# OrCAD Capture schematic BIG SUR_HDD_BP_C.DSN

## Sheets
1 P01 Cover Page: title: Big Sur; rev: C; company: Quanta
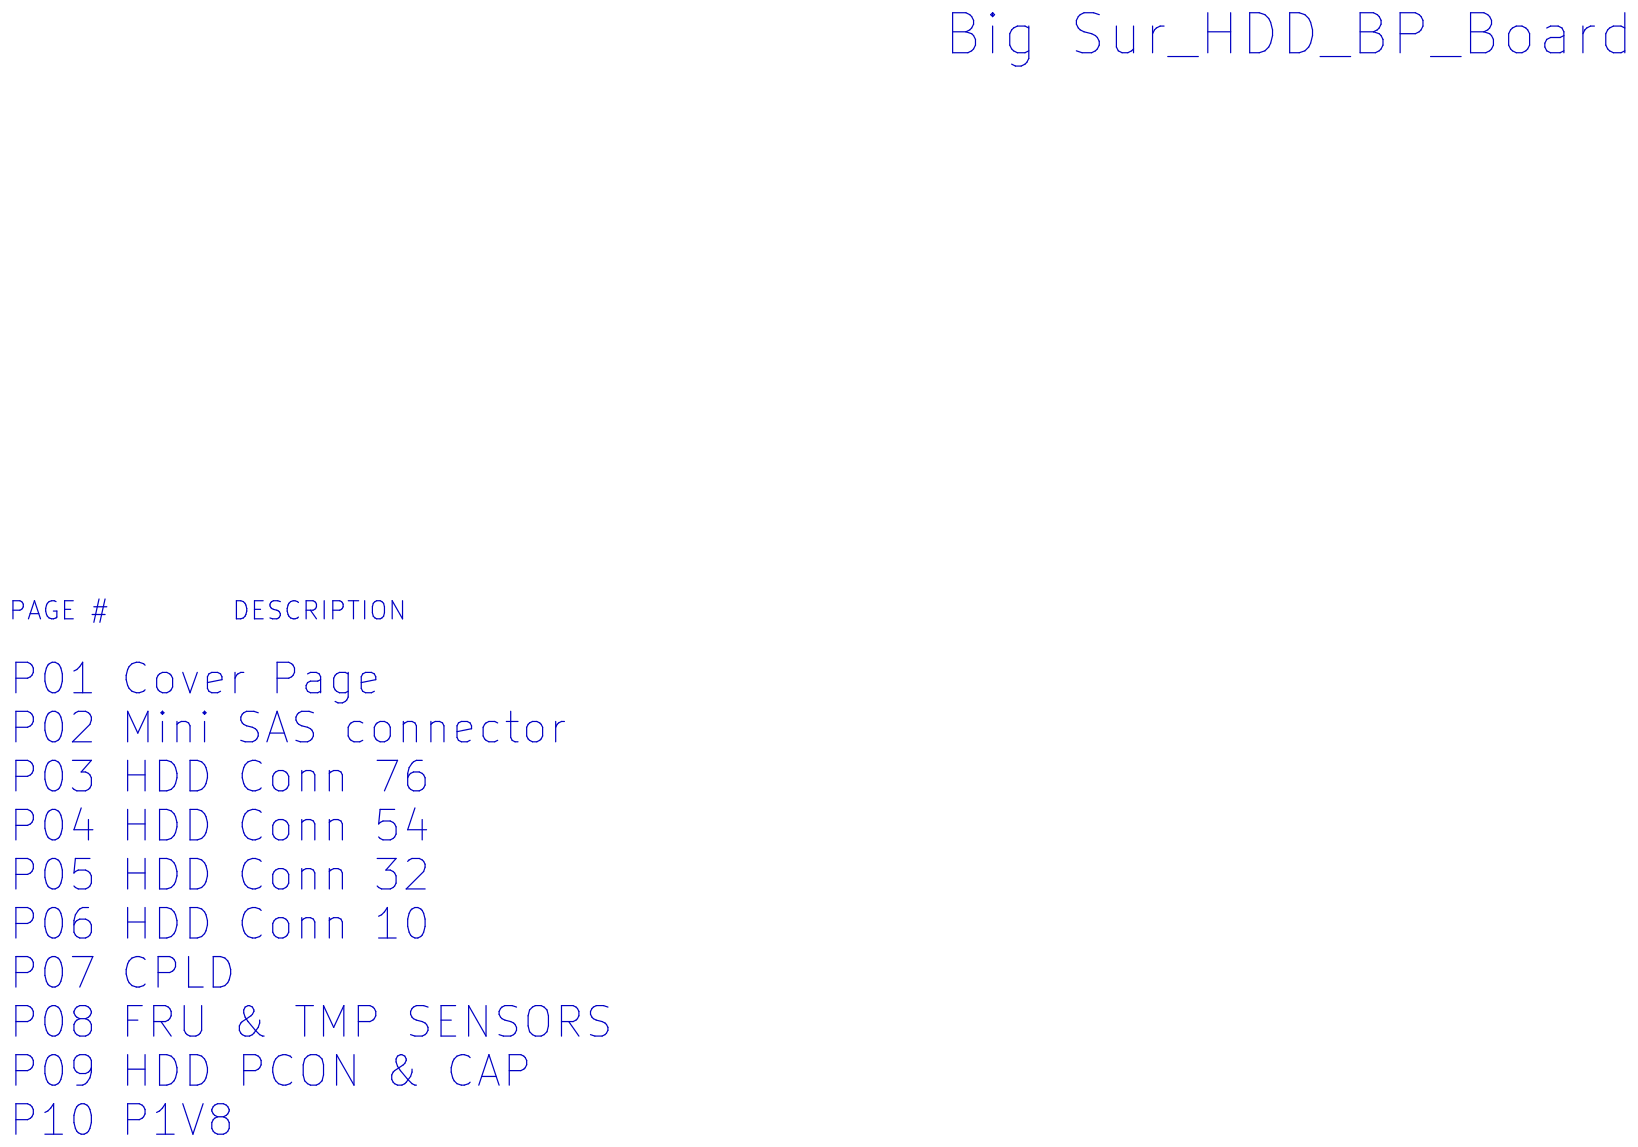
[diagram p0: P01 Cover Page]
2 P10 P1V8: size A
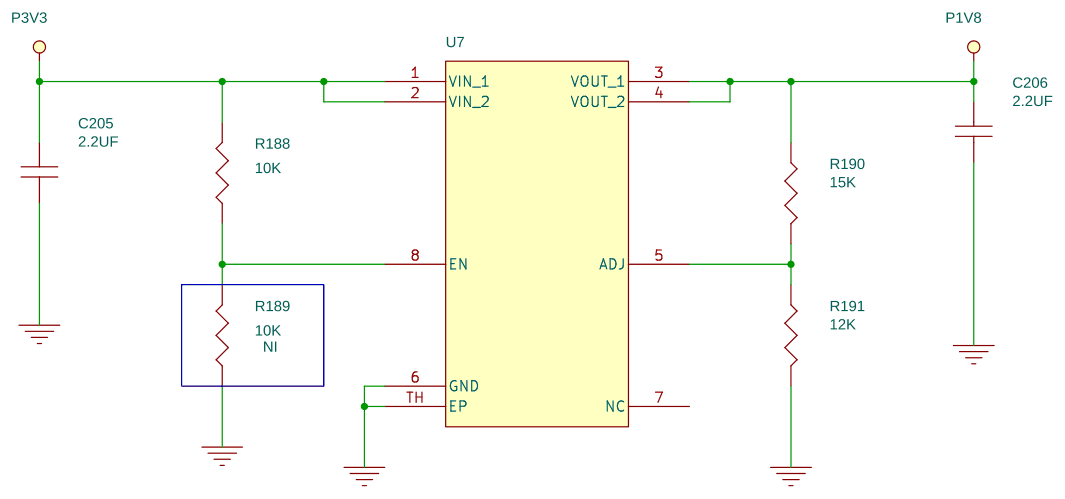
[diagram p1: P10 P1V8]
3 P02 Mini SAS connector: size B
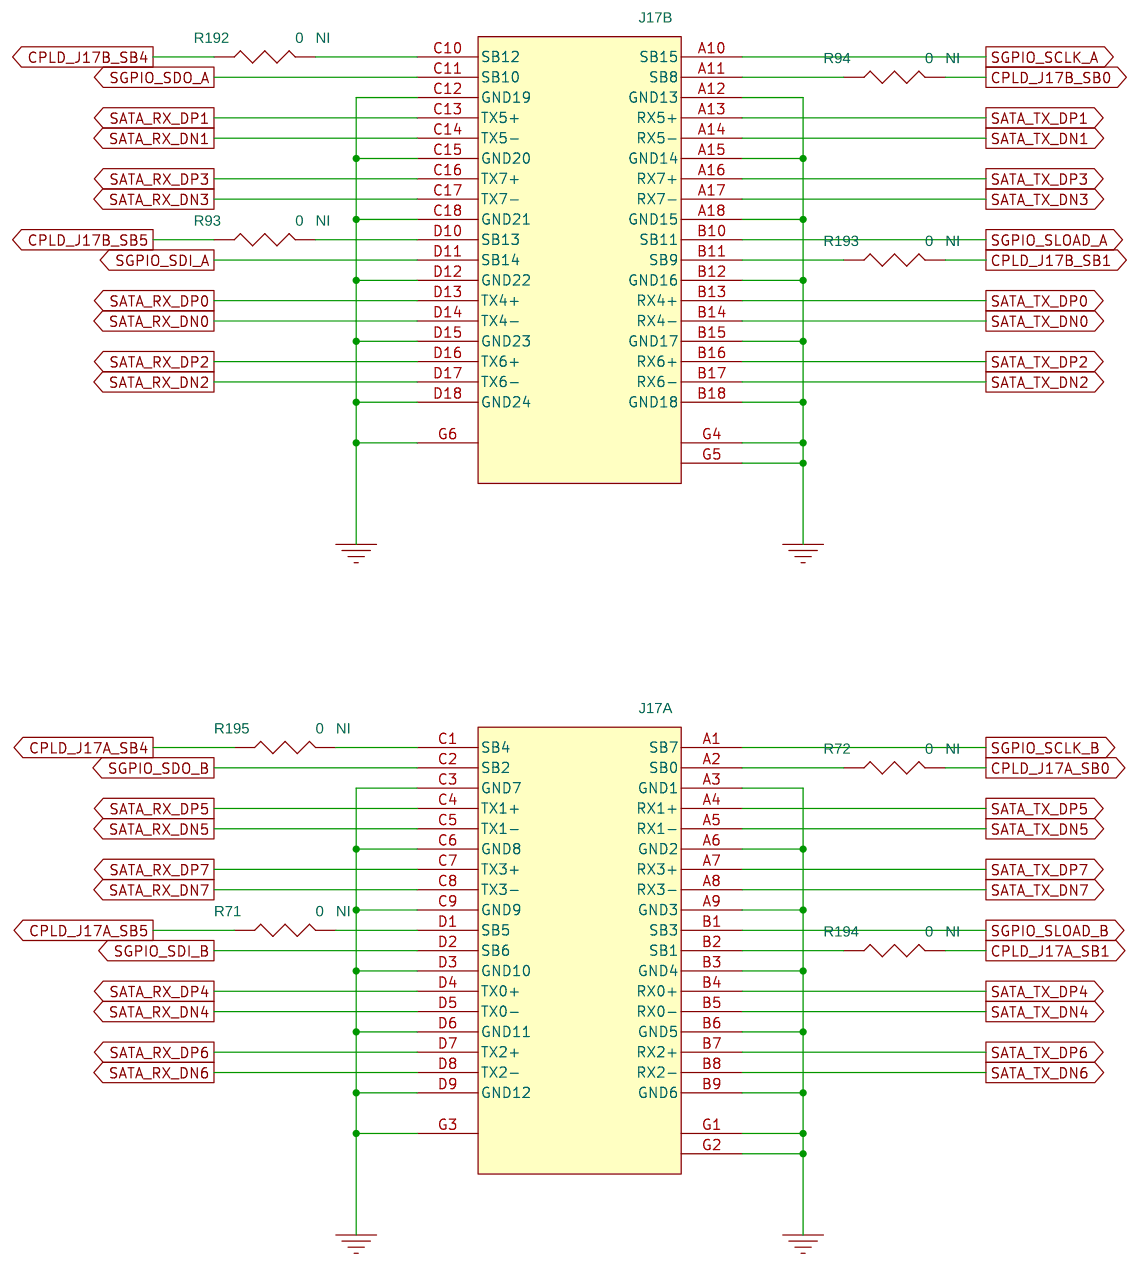
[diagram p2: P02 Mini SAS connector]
4 P03 HDD Conn 76: size C
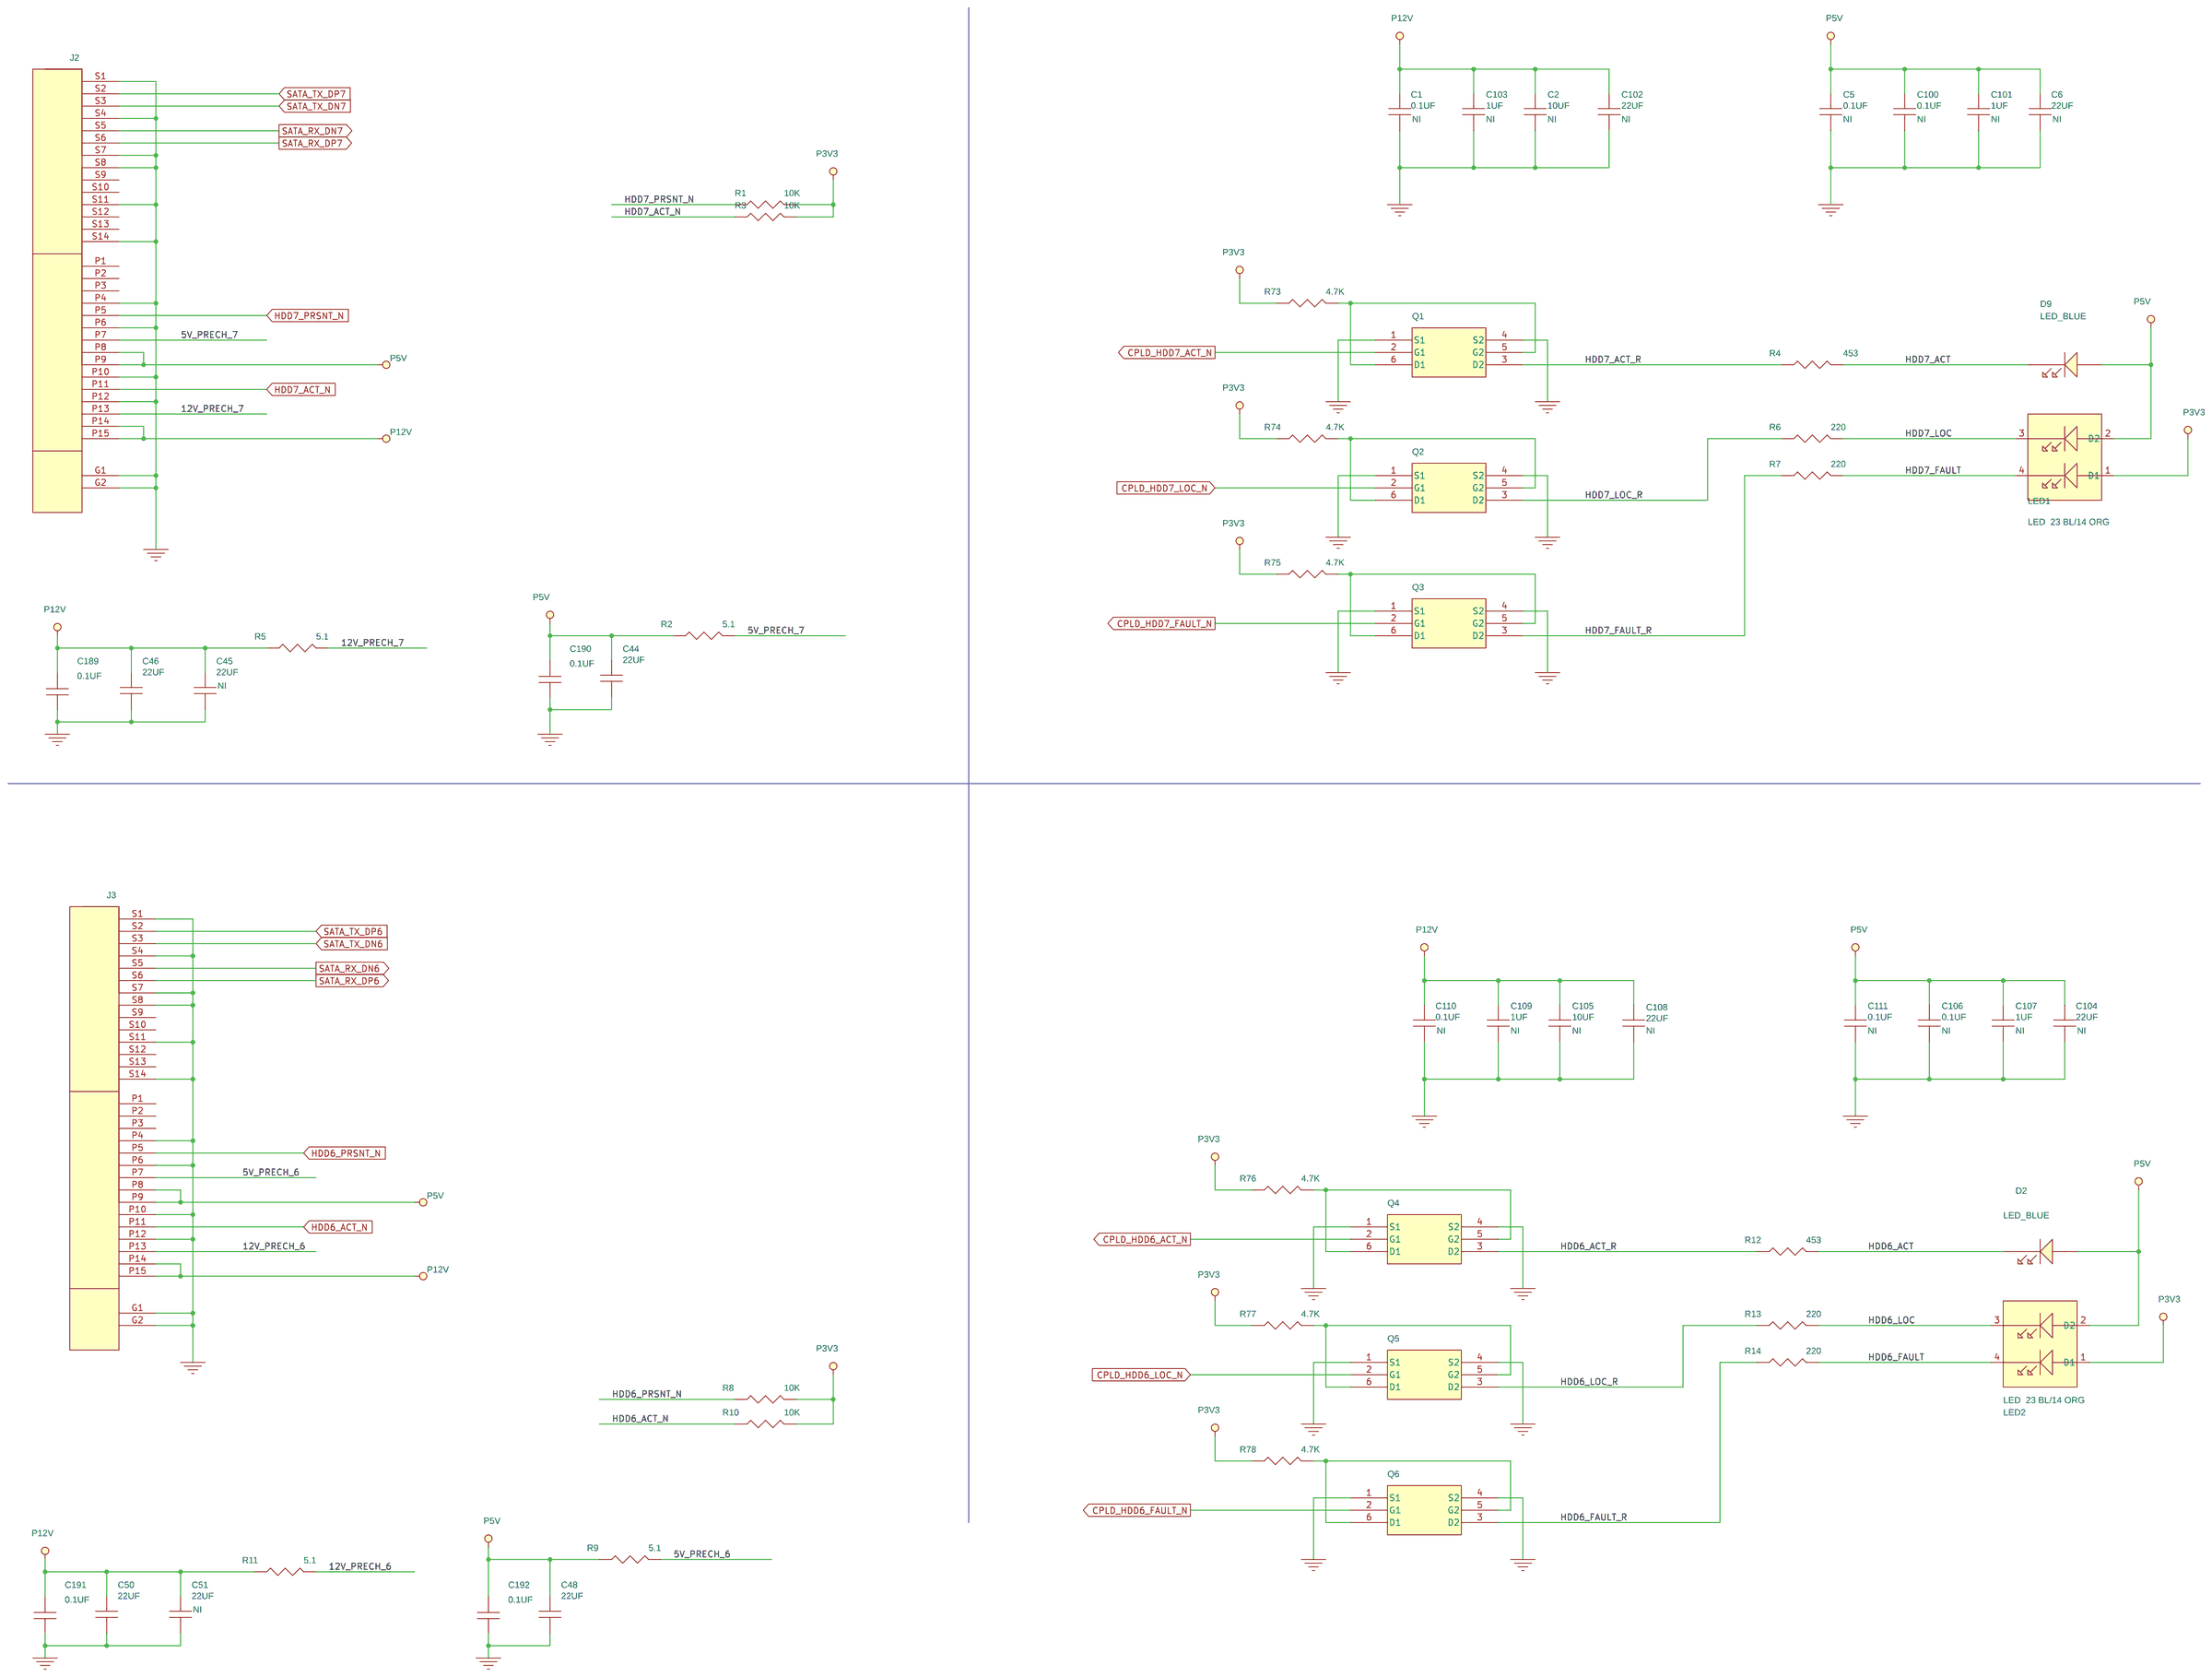
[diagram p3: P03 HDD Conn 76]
5 P04 HDD Conn 54: size C
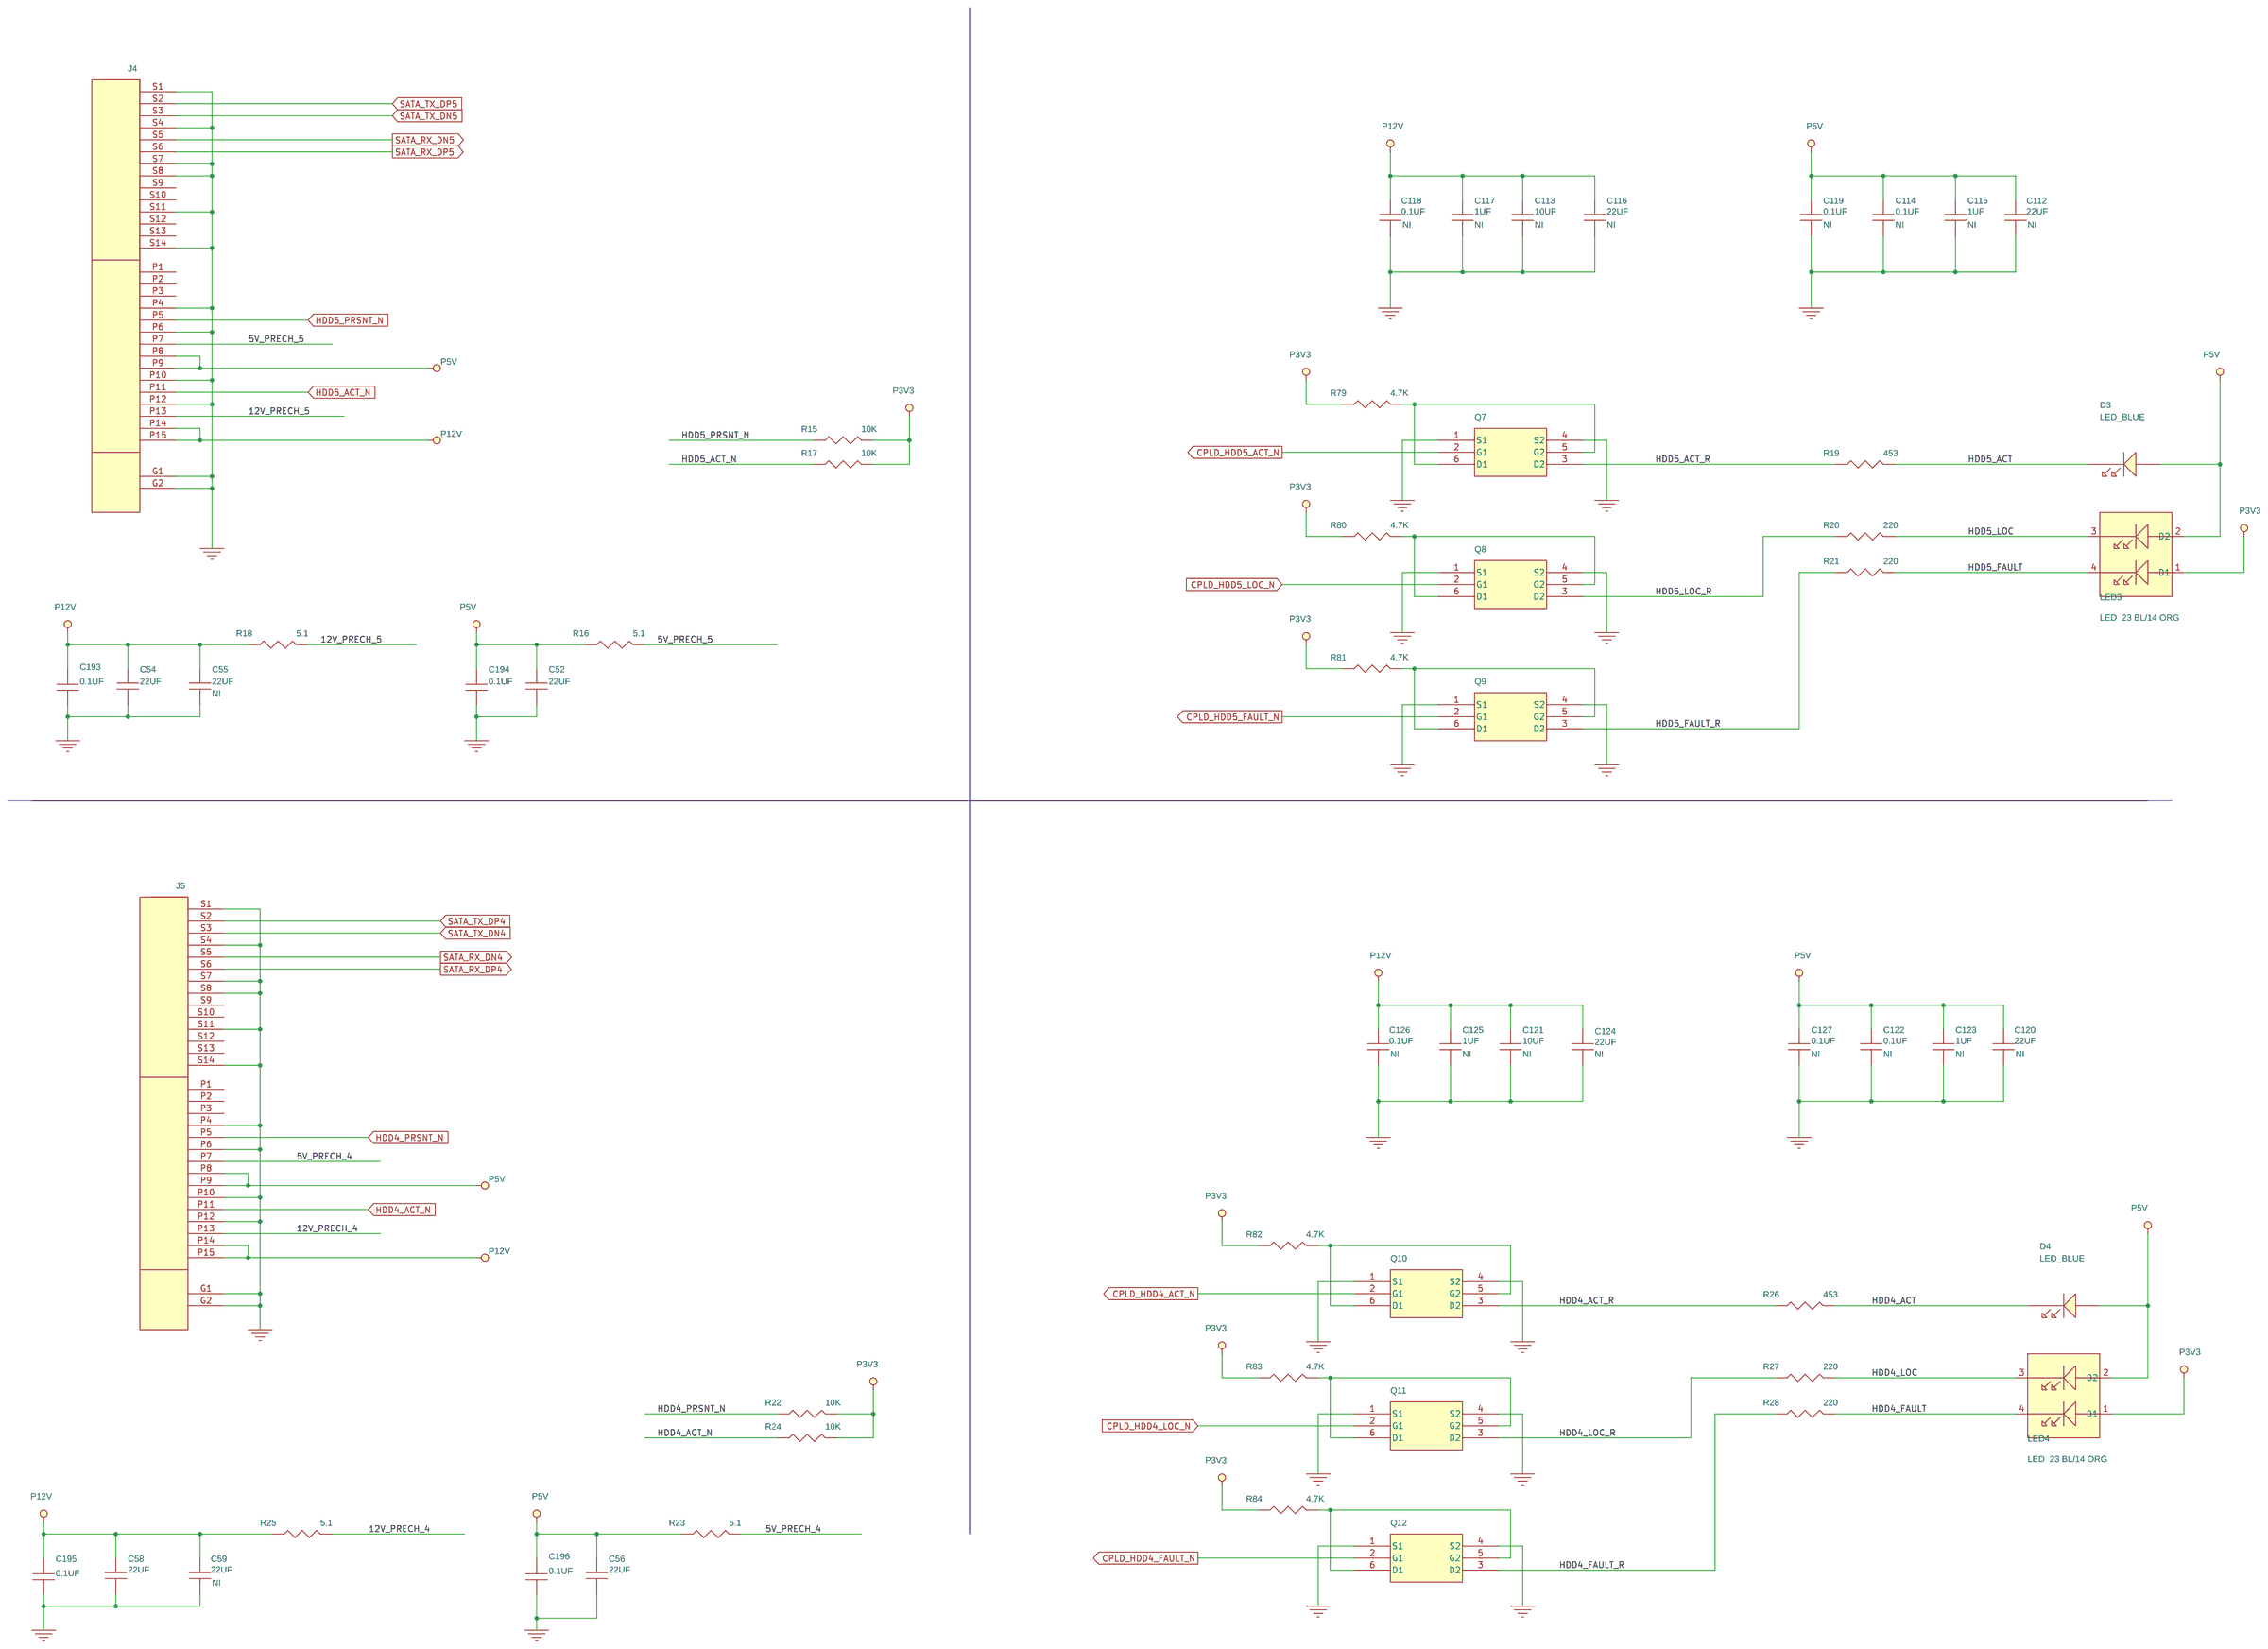
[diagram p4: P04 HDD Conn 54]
6 P05 HDD Conn 32: size C
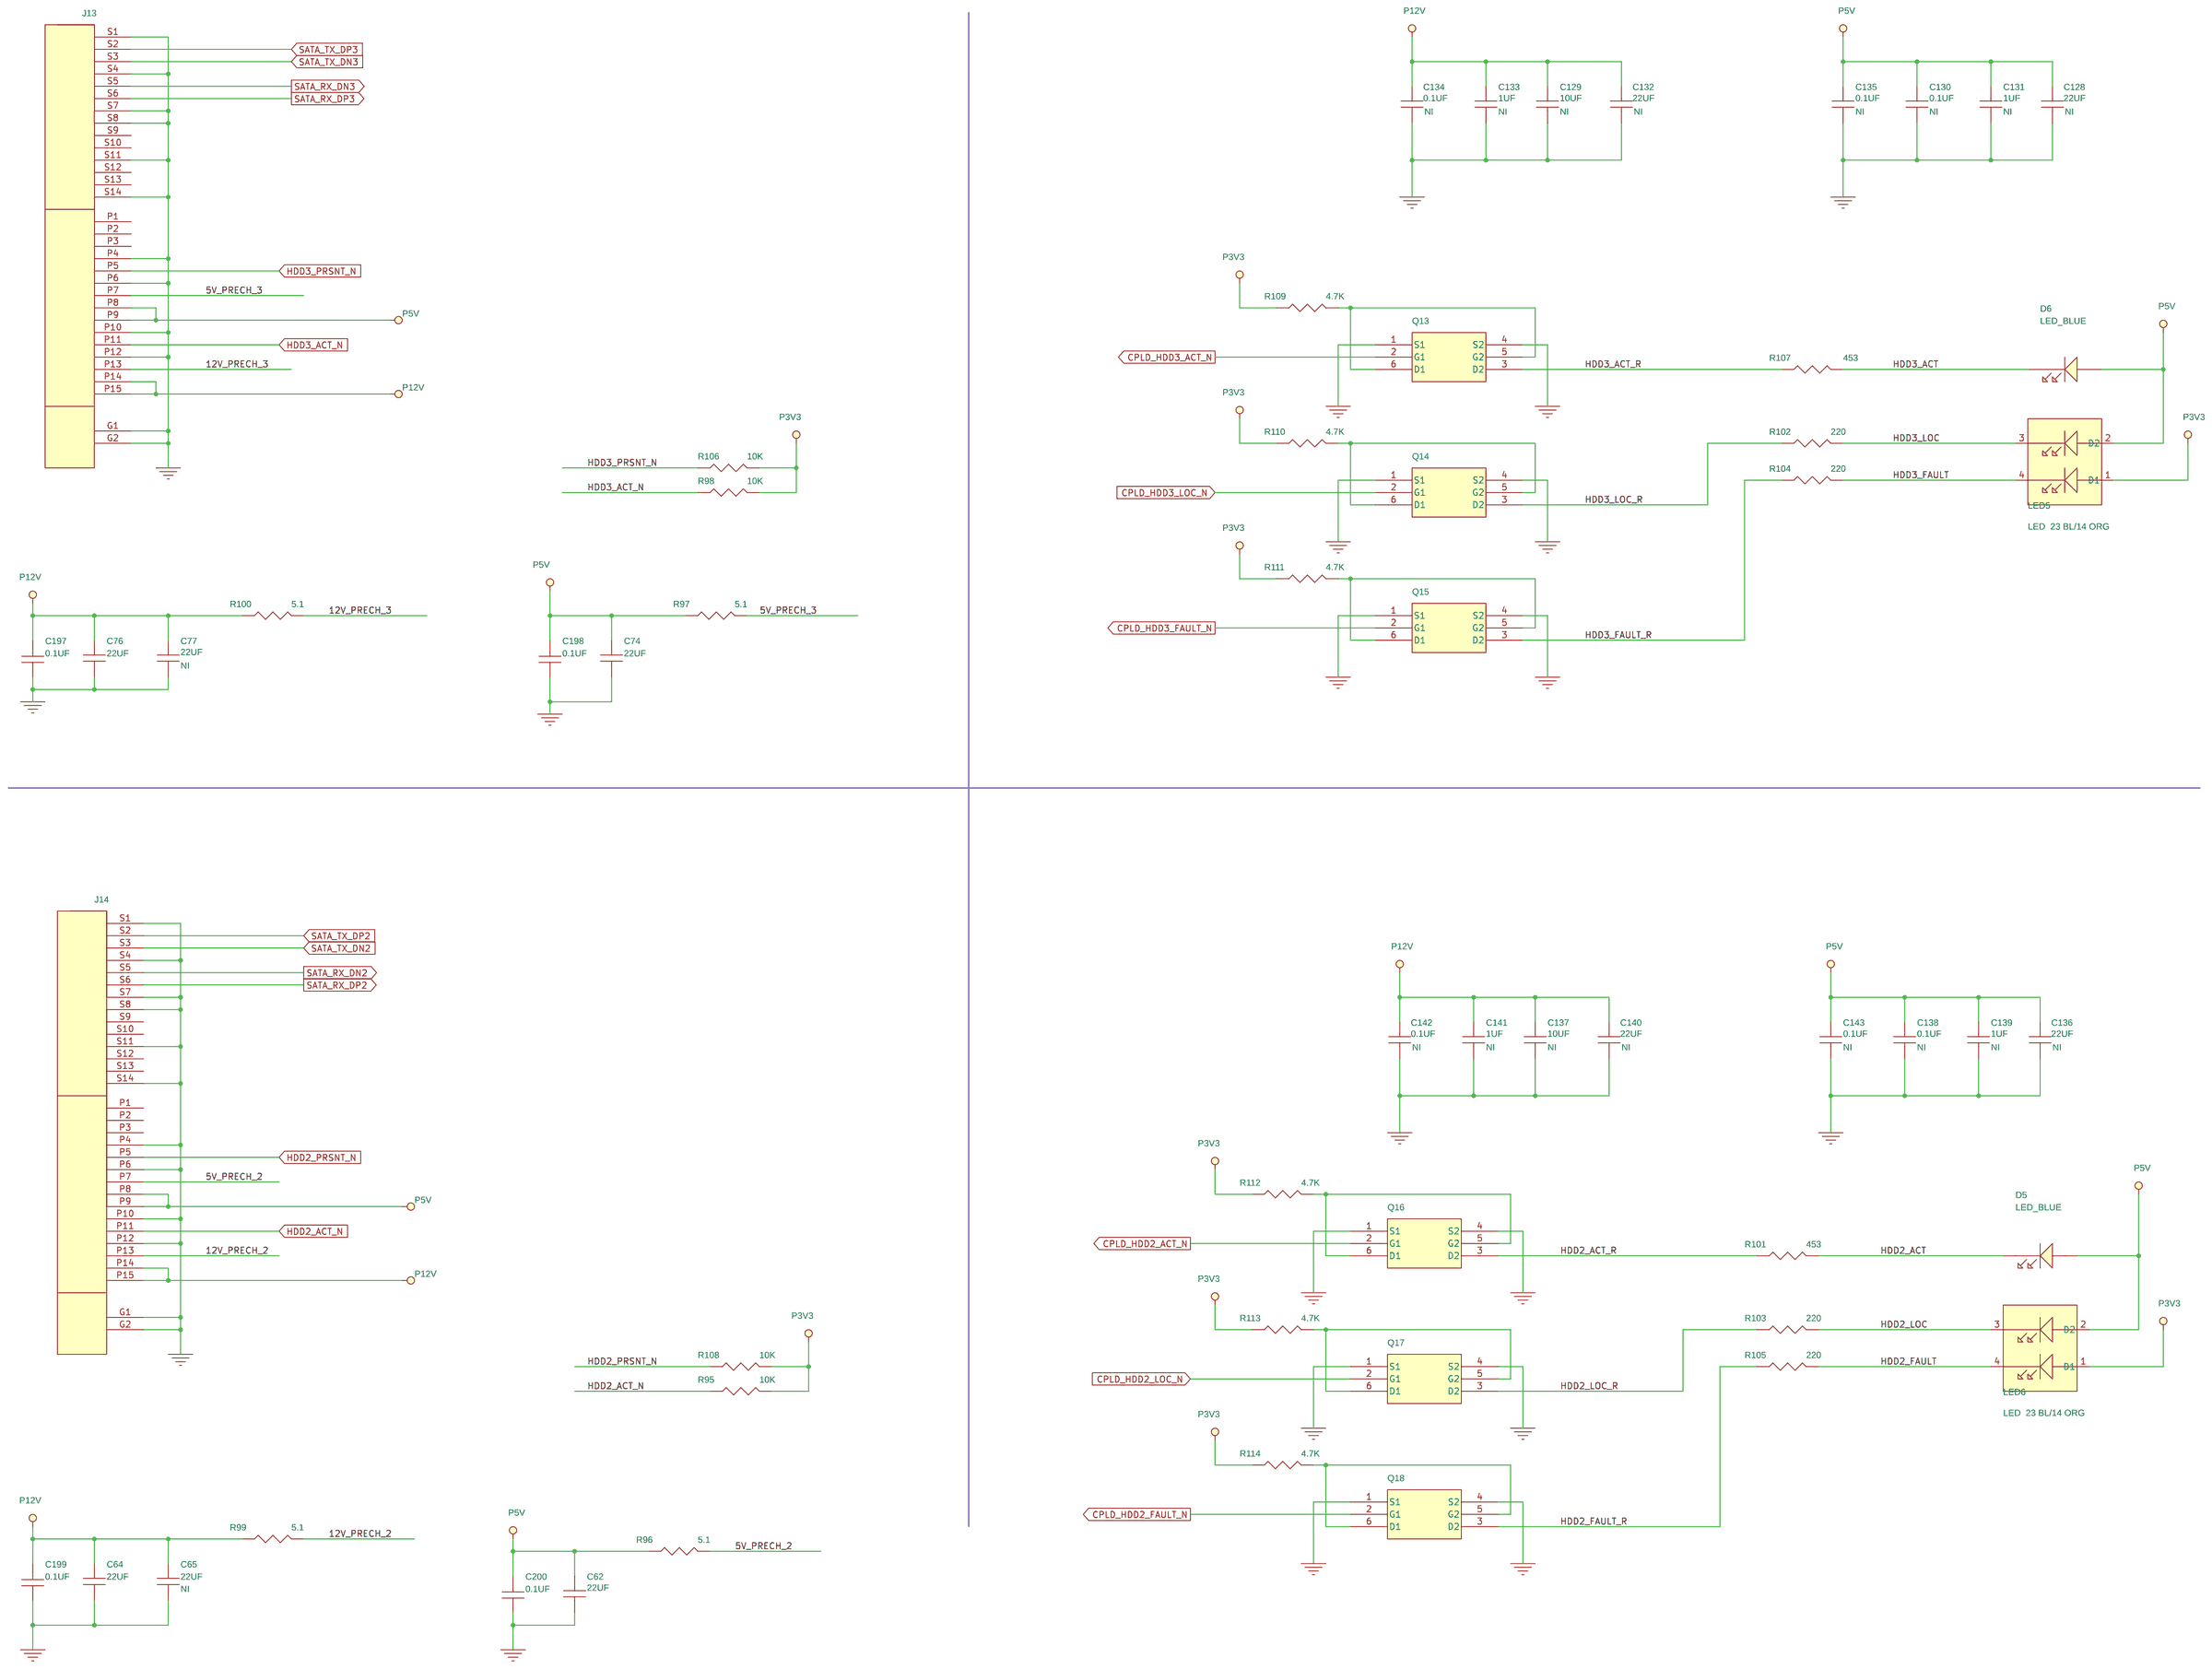
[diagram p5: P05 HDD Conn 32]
7 P06 HDD Conn 10: size C
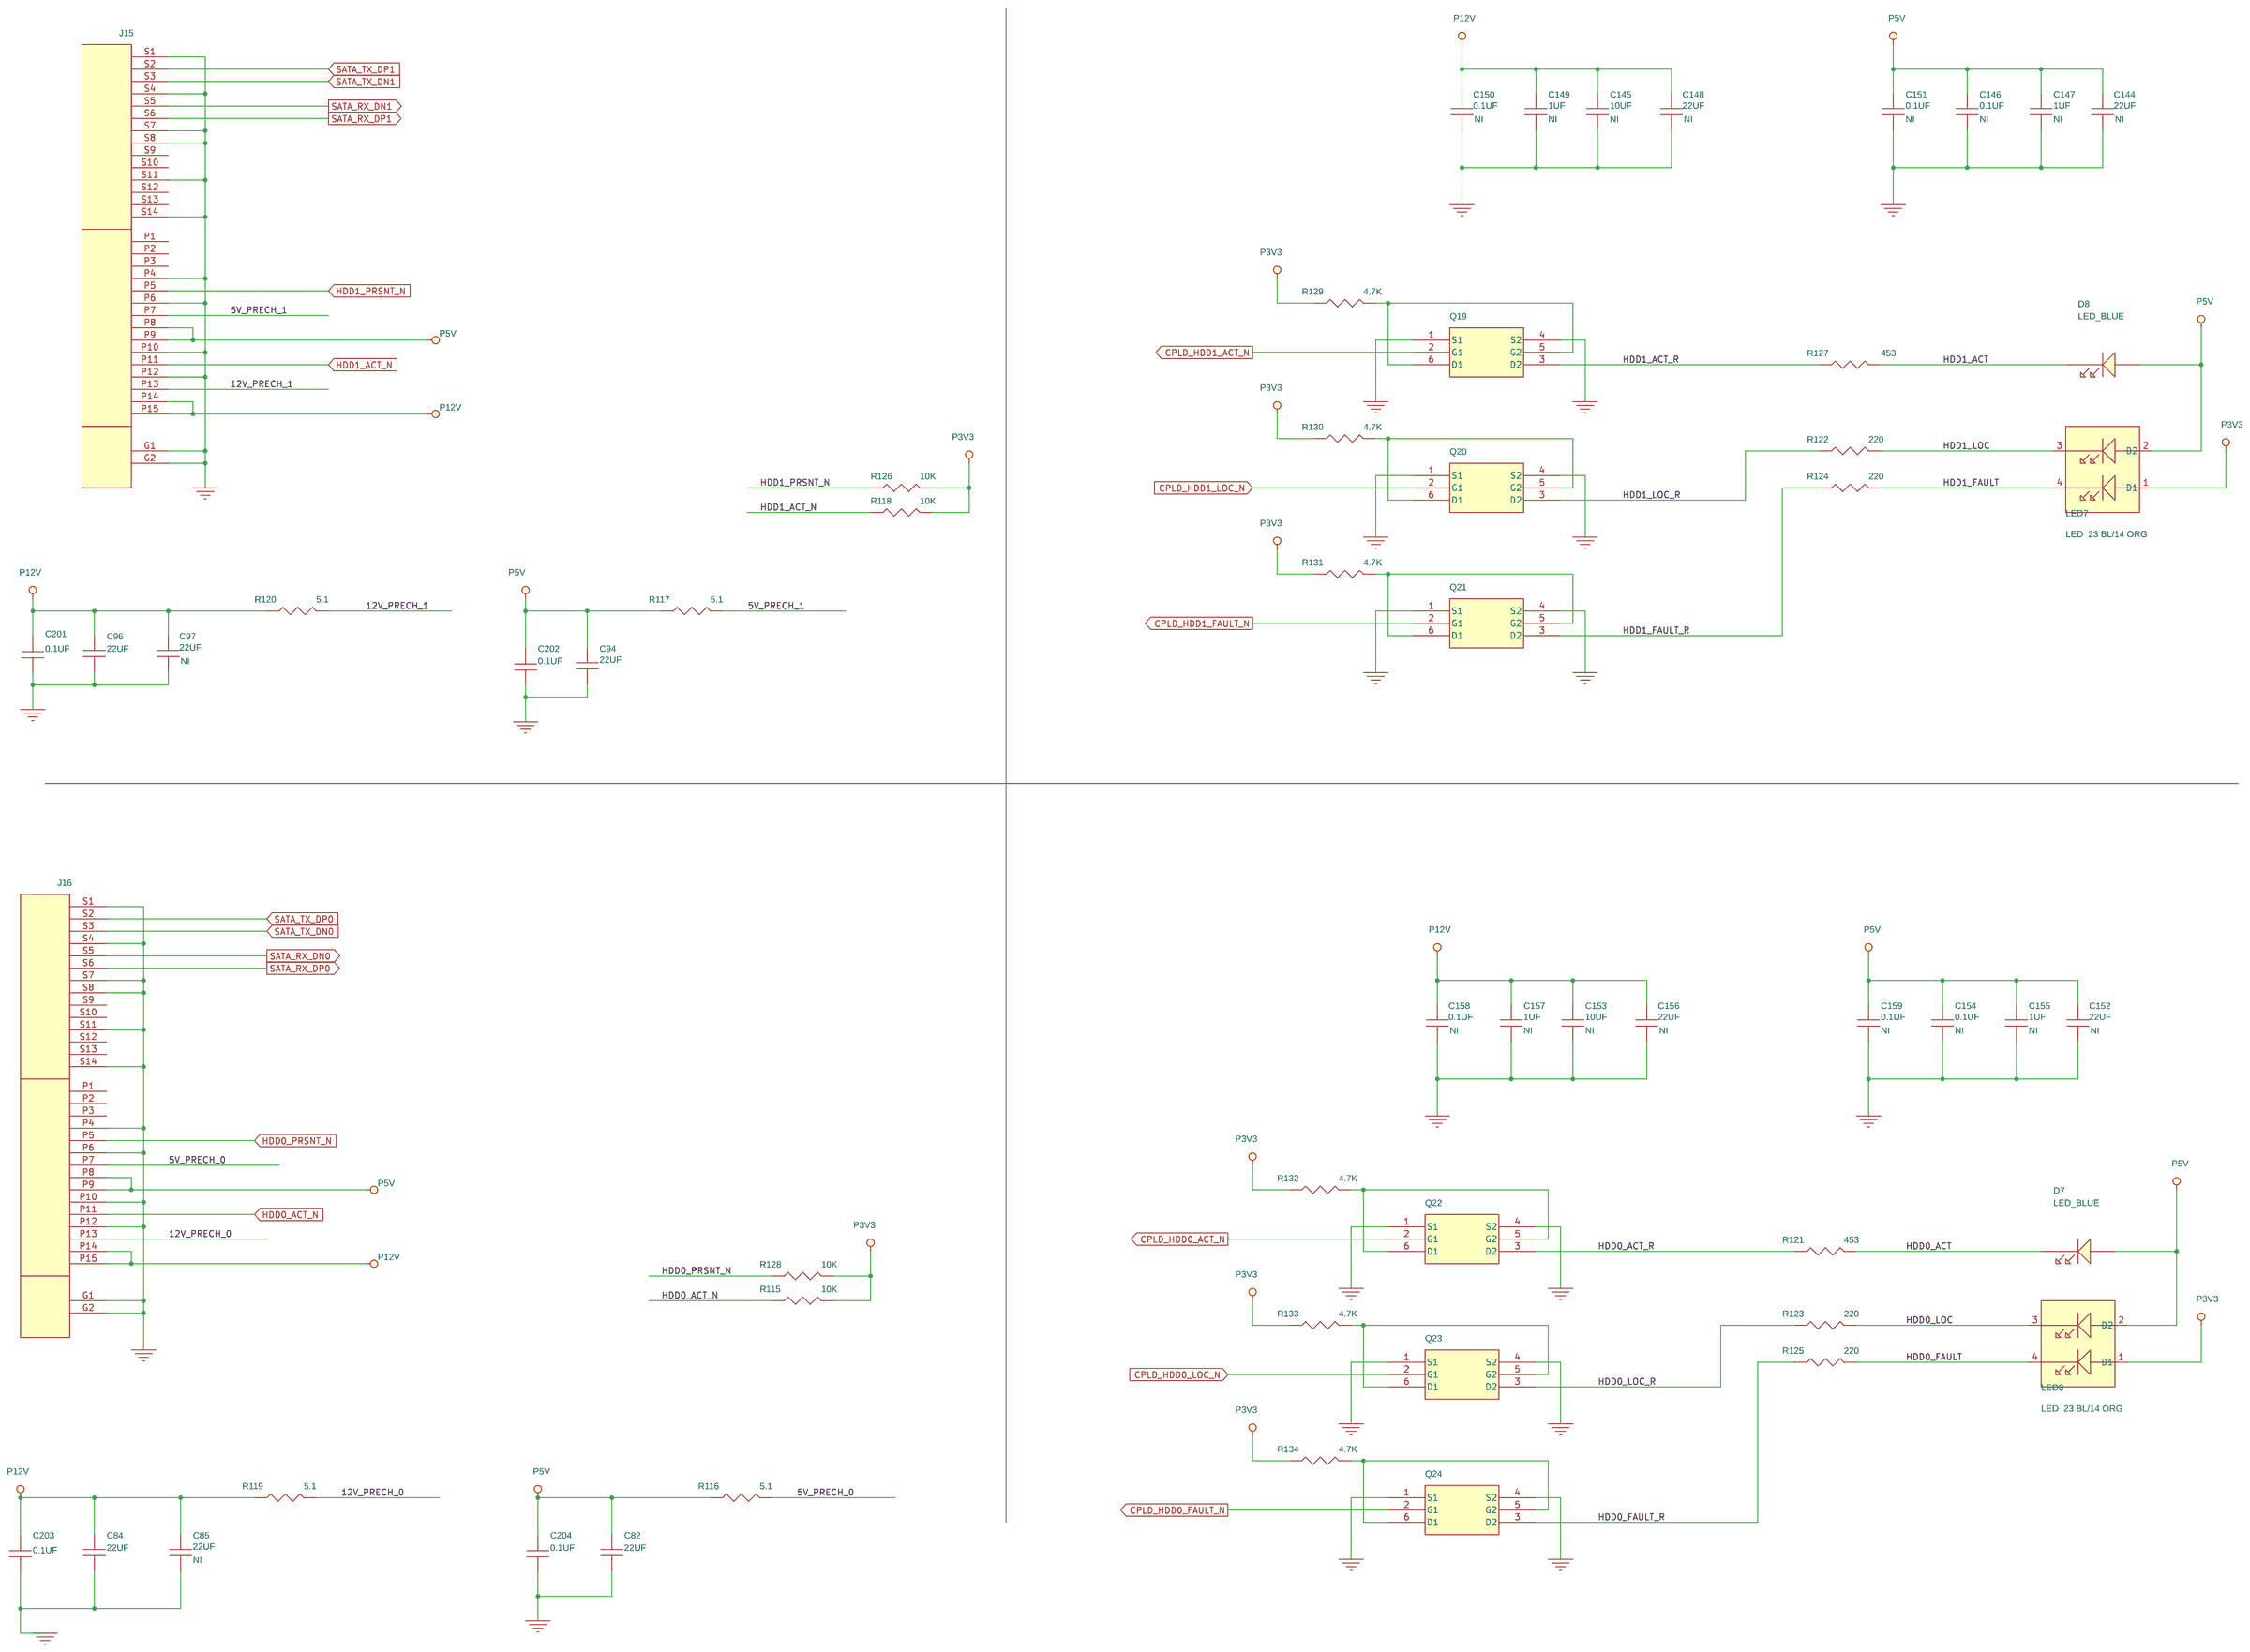
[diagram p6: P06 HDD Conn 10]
8 P07 CPLD: size Custom
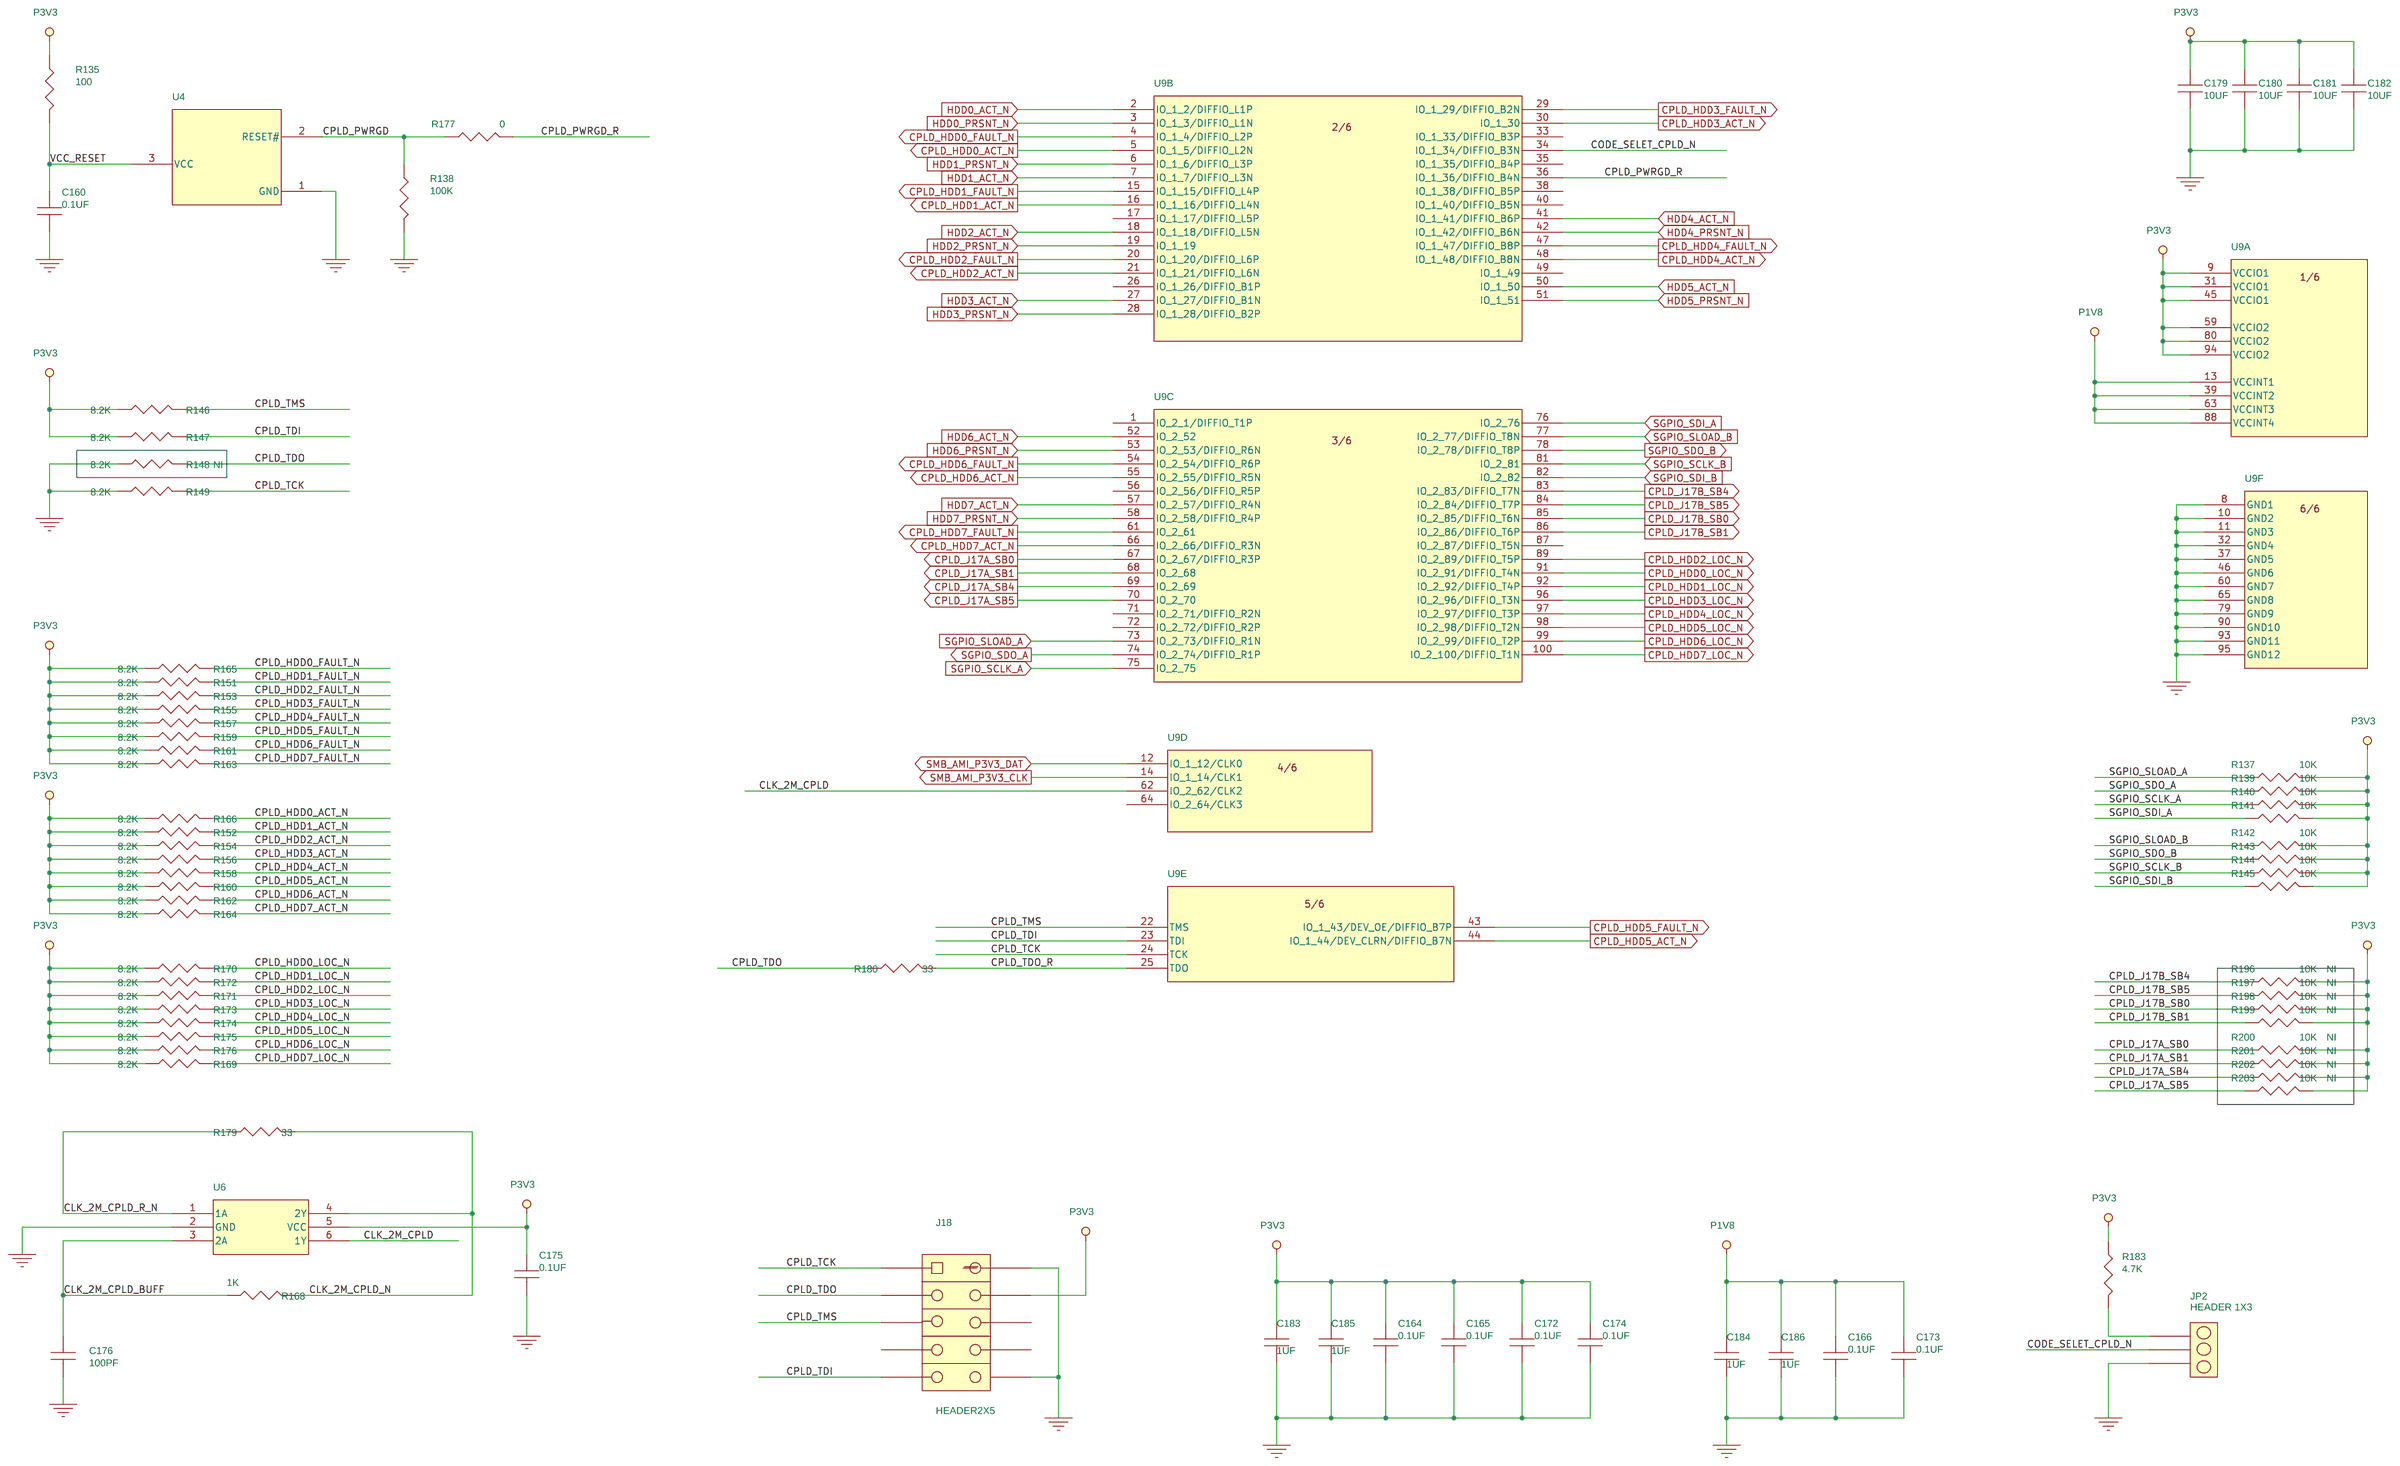
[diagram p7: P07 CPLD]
9 P08 FRU & TMP SENSORS: size Custom
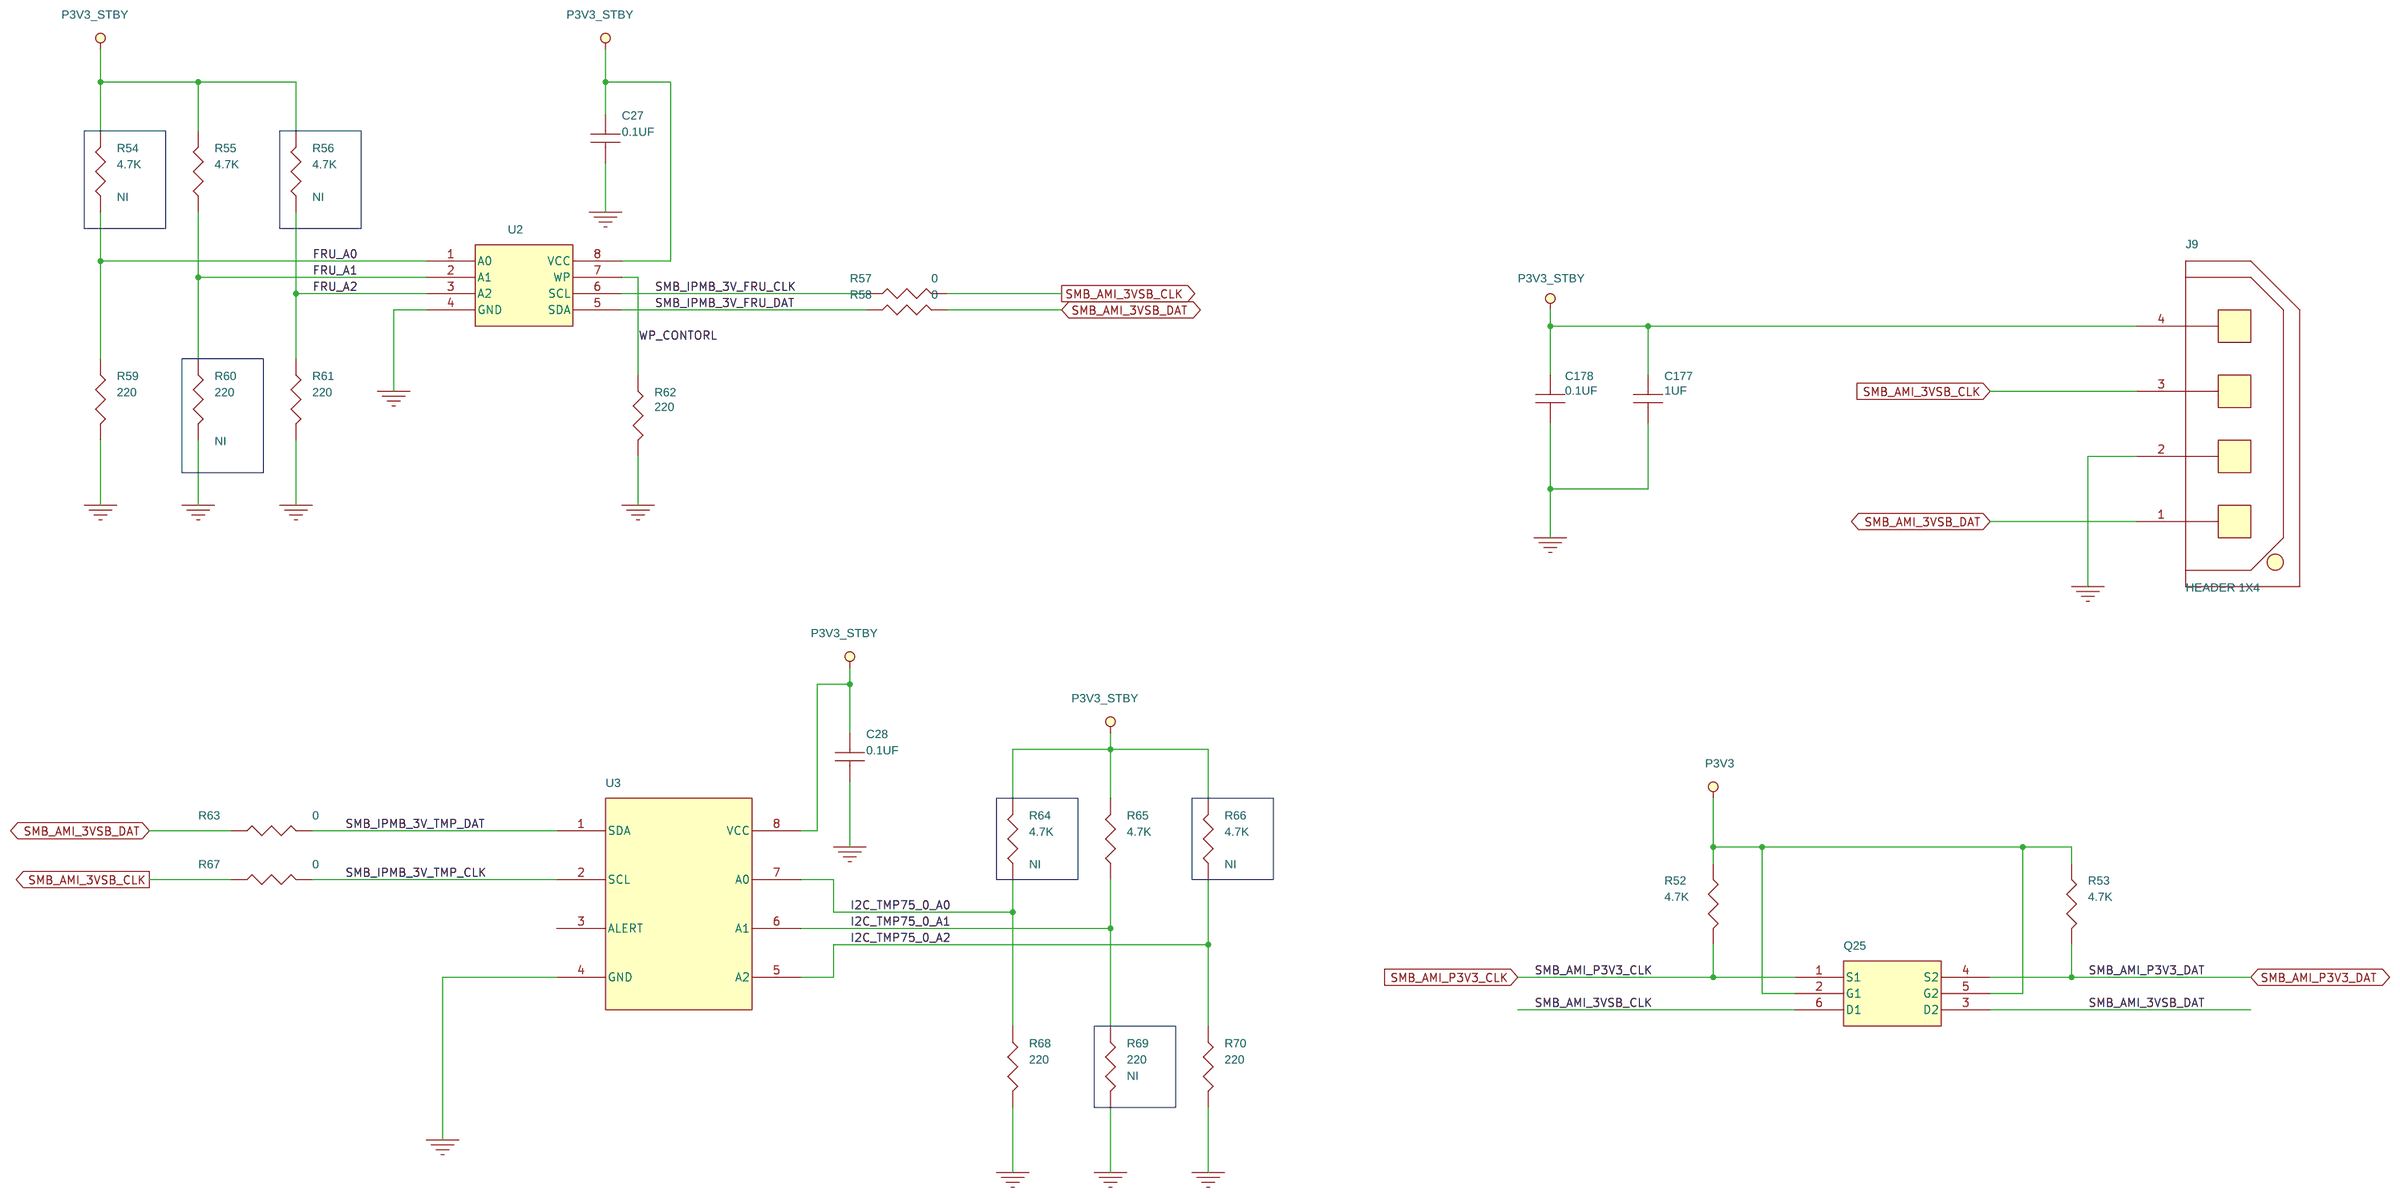
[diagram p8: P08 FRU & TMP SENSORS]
10 P09 HDD PCON & CAP: size Custom
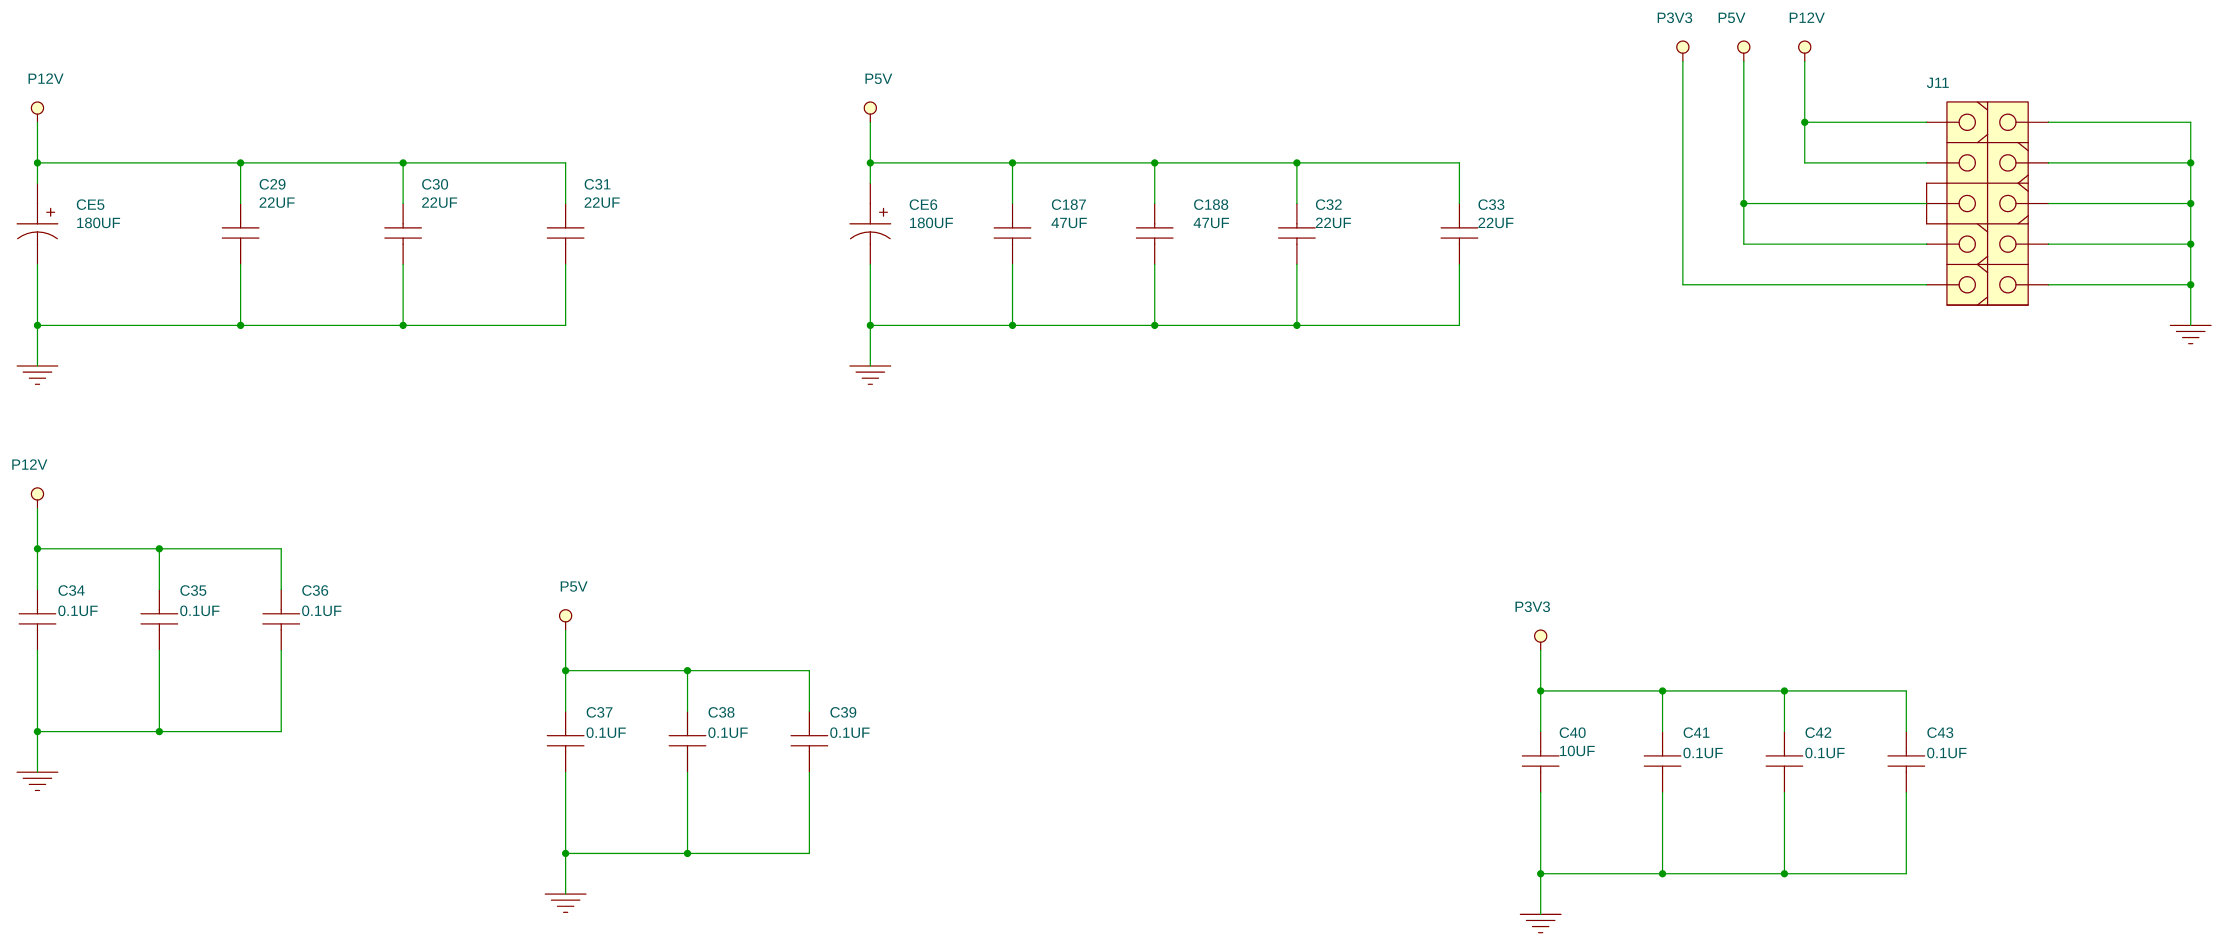
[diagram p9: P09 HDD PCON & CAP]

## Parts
sheet P02 Mini SAS connector
J17  SCONN72_G40H2232212HRC  [CON_F72S4H8D_P0-75W3-53_LDH]  (sections A,B)
R71  0  [R0402]
R72  0  [R0402]
R93  0  [R0402]
R94  0  [R0402]
R192  0  [R0402]
R193  0  [R0402]
R194  0  [R0402]
R195  0  [R0402]
sheet P03 HDD Conn 76
C1  0.1UF  [C0402]
C2  10UF  [C1206_H76]
C5  0.1UF  [C0402]
C6  22UF  [C1206_H66]
C44  22UF  [C0805_H61]
C45  22UF  [C0805_H61]
C46  22UF  [C0805_H61]
C48  22UF  [C0805_H61]
C50  22UF  [C0805_H61]
C51  22UF  [C0805_H61]
C100  0.1UF  [C0402]
C101  1UF  [C0603]
C102  22UF  [C1206_H76]
C103  1UF  [C0603]
C104  22UF  [C1206_H66]
C105  10UF  [C1206_H76]
C106  0.1UF  [C0402]
C107  1UF  [C0603]
C108  22UF  [C1206_H76]
C109  1UF  [C0603]
C110  0.1UF  [C0402]
C111  0.1UF  [C0402]
C189  0.1UF  [C0402]
C190  0.1UF  [C0402]
C191  0.1UF  [C0402]
C192  0.1UF  [C0402]
D2  LED_BLUE  [LED_170VY_H44]
D9  LED_BLUE  [LED_170VY_H44]
J2  SCONN29_787280002  [SAS29SXW]
J3  SCONN29_787280002  [SAS29SXW]
LED1  LED  23 BL/14 ORG  [LED_19223]
LED2  LED  23 BL/14 ORG  [LED_19223]
Q1  2N7002KDW  [SOT363XD]
Q2  2N7002KDW  [SOT363XD]
Q3  2N7002KDW  [SOT363XD]
Q4  2N7002KDW  [SOT363XD]
Q5  2N7002KDW  [SOT363XD]
Q6  2N7002KDW  [SOT363XD]
R1  10K  [R0402]
R2  5.1  [R1206]
R3  10K  [R0402]
R4  453  [R0603]
R5  5.1  [R1206]
R6  220  [R0603]
R7  220  [R0603]
R8  10K  [R0402]
R9  5.1  [R1206]
R10  10K  [R0402]
R11  5.1  [R1206]
R12  453  [R0603]
R13  220  [R0603]
R14  220  [R0603]
R73  4.7K  [R0402]
R74  4.7K  [R0402]
R75  4.7K  [R0402]
R76  4.7K  [R0402]
R77  4.7K  [R0402]
R78  4.7K  [R0402]
sheet P04 HDD Conn 54
C52  22UF  [C0805_H61]
C54  22UF  [C0805_H61]
C55  22UF  [C0805_H61]
C56  22UF  [C0805_H61]
C58  22UF  [C0805_H61]
C59  22UF  [C0805_H61]
C112  22UF  [C1206_H66]
C113  10UF  [C1206_H76]
C114  0.1UF  [C0402]
C115  1UF  [C0603]
C116  22UF  [C1206_H76]
C117  1UF  [C0603]
C118  0.1UF  [C0402]
C119  0.1UF  [C0402]
C120  22UF  [C1206_H66]
C121  10UF  [C1206_H76]
C122  0.1UF  [C0402]
C123  1UF  [C0603]
C124  22UF  [C1206_H76]
C125  1UF  [C0603]
C126  0.1UF  [C0402]
C127  0.1UF  [C0402]
C193  0.1UF  [C0402]
C194  0.1UF  [C0402]
C195  0.1UF  [C0402]
C196  0.1UF  [C0402]
D3  LED_BLUE  [LED_170VY_H44]
D4  LED_BLUE  [LED_170VY_H44]
J4  SCONN29_787280002  [SAS29SXW]
J5  SCONN29_787280002  [SAS29SXW]
LED3  LED  23 BL/14 ORG  [LED_19223]
LED4  LED  23 BL/14 ORG  [LED_19223]
Q7  2N7002KDW  [SOT363XD]
Q8  2N7002KDW  [SOT363XD]
Q9  2N7002KDW  [SOT363XD]
Q10  2N7002KDW  [SOT363XD]
Q11  2N7002KDW  [SOT363XD]
Q12  2N7002KDW  [SOT363XD]
R15  10K  [R0402]
R16  5.1  [R1206]
R17  10K  [R0402]
R18  5.1  [R1206]
R19  453  [R0603]
R20  220  [R0603]
R21  220  [R0603]
R22  10K  [R0402]
R23  5.1  [R1206]
R24  10K  [R0402]
R25  5.1  [R1206]
R26  453  [R0603]
R27  220  [R0603]
R28  220  [R0603]
R79  4.7K  [R0402]
R80  4.7K  [R0402]
R81  4.7K  [R0402]
R82  4.7K  [R0402]
R83  4.7K  [R0402]
R84  4.7K  [R0402]
sheet P05 HDD Conn 32
C62  22UF  [C0805_H61]
C64  22UF  [C0805_H61]
C65  22UF  [C0805_H61]
C74  22UF  [C0805_H61]
C76  22UF  [C0805_H61]
C77  22UF  [C0805_H61]
C128  22UF  [C1206_H66]
C129  10UF  [C1206_H76]
C130  0.1UF  [C0402]
C131  1UF  [C0603]
C132  22UF  [C1206_H76]
C133  1UF  [C0603]
C134  0.1UF  [C0402]
C135  0.1UF  [C0402]
C136  22UF  [C1206_H66]
C137  10UF  [C1206_H76]
C138  0.1UF  [C0402]
C139  1UF  [C0603]
C140  22UF  [C1206_H76]
C141  1UF  [C0603]
C142  0.1UF  [C0402]
C143  0.1UF  [C0402]
C197  0.1UF  [C0402]
C198  0.1UF  [C0402]
C199  0.1UF  [C0402]
C200  0.1UF  [C0402]
D5  LED_BLUE  [LED_170VY_H44]
D6  LED_BLUE  [LED_170VY_H44]
J13  SCONN29_787280002  [SAS29SXW]
J14  SCONN29_787280002  [SAS29SXW]
LED5  LED  23 BL/14 ORG  [LED_19223]
LED6  LED  23 BL/14 ORG  [LED_19223]
Q13  2N7002KDW  [SOT363XD]
Q14  2N7002KDW  [SOT363XD]
Q15  2N7002KDW  [SOT363XD]
Q16  2N7002KDW  [SOT363XD]
Q17  2N7002KDW  [SOT363XD]
Q18  2N7002KDW  [SOT363XD]
R95  10K  [R0402]
R96  5.1  [R1206]
R97  5.1  [R1206]
R98  10K  [R0402]
R99  5.1  [R1206]
R100  5.1  [R1206]
R101  453  [R0603]
R102  220  [R0603]
R103  220  [R0603]
R104  220  [R0603]
R105  220  [R0603]
R106  10K  [R0402]
R107  453  [R0603]
R108  10K  [R0402]
R109  4.7K  [R0402]
R110  4.7K  [R0402]
R111  4.7K  [R0402]
R112  4.7K  [R0402]
R113  4.7K  [R0402]
R114  4.7K  [R0402]
sheet P06 HDD Conn 10
C82  22UF  [C0805_H61]
C84  22UF  [C0805_H61]
C85  22UF  [C0805_H61]
C94  22UF  [C0805_H61]
C96  22UF  [C0805_H61]
C97  22UF  [C0805_H61]
C144  22UF  [C1206_H66]
C145  10UF  [C1206_H76]
C146  0.1UF  [C0402]
C147  1UF  [C0603]
C148  22UF  [C1206_H76]
C149  1UF  [C0603]
C150  0.1UF  [C0402]
C151  0.1UF  [C0402]
C152  22UF  [C1206_H66]
C153  10UF  [C1206_H76]
C154  0.1UF  [C0402]
C155  1UF  [C0603]
C156  22UF  [C1206_H76]
C157  1UF  [C0603]
C158  0.1UF  [C0402]
C159  0.1UF  [C0402]
C201  0.1UF  [C0402]
C202  0.1UF  [C0402]
C203  0.1UF  [C0402]
C204  0.1UF  [C0402]
D7  LED_BLUE  [LED_170VY_H44]
D8  LED_BLUE  [LED_170VY_H44]
J15  SCONN29_787280002  [SAS29SXW]
J16  SCONN29_787280002  [SAS29SXW]
LED7  LED  23 BL/14 ORG  [LED_19223]
LED8  LED  23 BL/14 ORG  [LED_19223]
Q19  2N7002KDW  [SOT363XD]
Q20  2N7002KDW  [SOT363XD]
Q21  2N7002KDW  [SOT363XD]
Q22  2N7002KDW  [SOT363XD]
Q23  2N7002KDW  [SOT363XD]
Q24  2N7002KDW  [SOT363XD]
R115  10K  [R0402]
R116  5.1  [R1206]
R117  5.1  [R1206]
R118  10K  [R0402]
R119  5.1  [R1206]
R120  5.1  [R1206]
R121  453  [R0603]
R122  220  [R0603]
R123  220  [R0603]
R124  220  [R0603]
R125  220  [R0603]
R126  10K  [R0402]
R127  453  [R0603]
R128  10K  [R0402]
R129  4.7K  [R0402]
R130  4.7K  [R0402]
R131  4.7K  [R0402]
R132  4.7K  [R0402]
R133  4.7K  [R0402]
R134  4.7K  [R0402]
sheet P07 CPLD
C160  0.1UF  [C0402]
C164  0.1UF  [C0402]
C165  0.1UF  [C0402]
C166  0.1UF  [C0402]
C172  0.1UF  [C0402]
C173  0.1UF  [C0402]
C174  0.1UF  [C0402]
C175  0.1UF  [C0402]
C176  100PF  [C0402]
C179  10UF  [C0603]
C180  10UF  [C0603]
C181  10UF  [C0603]
C182  10UF  [C0603]
C183  1UF  [C0402]
C184  1UF  [C0402]
C185  1UF  [C0402]
C186  1UF  [C0402]
J18  HEADER2X5  [HEADER2X5XB]
JP2  HEADER 1X3  [HEADER1X3XB]
R135  100  [R0402]
R137  10K  [R0402]
R138  100K  [R0201]
R139  10K  [R0402]
R140  10K  [R0402]
R141  10K  [R0402]
R142  10K  [R0402]
R143  10K  [R0402]
R144  10K  [R0402]
R145  10K  [R0402]
R146  8.2K  [R0402]
R147  8.2K  [R0402]
R148  8.2K  [R0402]
R149  8.2K  [R0402]
R151  8.2K  [R0402]
R152  8.2K  [R0402]
R153  8.2K  [R0402]
R154  8.2K  [R0402]
R155  8.2K  [R0402]
R156  8.2K  [R0402]
R157  8.2K  [R0402]
R158  8.2K  [R0402]
R159  8.2K  [R0402]
R160  8.2K  [R0402]
R161  8.2K  [R0402]
R162  8.2K  [R0402]
R163  8.2K  [R0402]
R164  8.2K  [R0402]
R165  8.2K  [R0402]
R166  8.2K  [R0402]
R168  1K  [R0402]
R169  8.2K  [R0402]
R170  8.2K  [R0402]
R171  8.2K  [R0402]
R172  8.2K  [R0402]
R173  8.2K  [R0402]
R174  8.2K  [R0402]
R175  8.2K  [R0402]
R176  8.2K  [R0402]
R177  0  [R0402]
R179  33  [R0402]
R180  33  [R0402]
R183  4.7K  [R0402]
R196  10K  [R0402]
R197  10K  [R0402]
R198  10K  [R0402]
R199  10K  [R0402]
R200  10K  [R0402]
R201  10K  [R0402]
R202  10K  [R0402]
R203  10K  [R0402]
U4  MAX809SEUR+  [SOT23_123]
U6  74LVC2G14GW  [SOT363]
U9  IC  [TQFP100_H54A]  (sections A,B,C,D,E,F)
sheet P08 FRU & TMP SENSORS
C27  0.1UF  [C0603]
C28  0.1UF  [C0603]
C177  1UF  [C0603]
C178  0.1UF  [C0402]
J9  HEADER 1X4  [HEADER1X4BHXA]
Q25  2N7002KDW  [SOT363XD]
R52  4.7K  [R0402]
R53  4.7K  [R0402]
R54  4.7K  [R0402]
R55  4.7K  [R0402]
R56  4.7K  [R0402]
R57  0  [R0402]
R58  0  [R0402]
R59  220  [R0402]
R60  220  [R0402]
R61  220  [R0402]
R62  220  [R0402]
R63  0  [R0402]
R64  4.7K  [R0402]
R65  4.7K  [R0402]
R66  4.7K  [R0402]
R67  0  [R0402]
R68  220  [R0402]
R69  220  [R0402]
R70  220  [R0402]
U2  M24C04-WMN6TP  [SOIC8]
U3  TMP75AIDR  [SOIC8]
sheet P09 HDD PCON & CAP
C29  22UF  [C1206_H76]
C30  22UF  [C1206_H76]
C31  22UF  [C1206_H76]
C32  22UF  [C1206_H66]
C33  22UF  [C1206_H66]
C34  0.1UF  [C0603]
C35  0.1UF  [C0603]
C36  0.1UF  [C0603]
C37  0.1UF  [C0603]
C38  0.1UF  [C0603]
C39  0.1UF  [C0603]
C40  10UF  [C0805_H61]
C41  0.1UF  [C0603]
C42  0.1UF  [C0603]
C43  0.1UF  [C0603]
C187  47UF  [C1206_H76]
C188  47UF  [C1206_H76]
CE5  180UF  [EC83_248_232S]
CE6  180UF  [EC83_248_232S]
J11  CONN10_HM3505E  [CON_PWR2X5]
sheet P10 P1V8
C205  2.2UF  [C0603]
C206  2.2UF  [C0603]
R188  10K  [R0402]
R189  10K  [R0402]
R190  15K  [R0402]
R191  12K  [R0402]
U7  IC  [VDFN8_TH]

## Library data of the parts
J17 = SCONN72_G40H2232212HRC: Part_Type: *LF_Connector
R54 R56 R60 R64 R66 R69 R71 R72 R93 R94 R148 R189 R192-R203 = R: Not_insert: NI; Part_Type: *LF_Resistor; WATTAGE: 1/16W
C1 C5 C100 C106 C110 C111 C114 C118 C119 C122 C126 C127 C130 C134 C135 C138 C142 C143 C146 C150 C151 C154 C158 C159 = CAP_NP: Not_insert: NI; Part_Type: *LF_C0402
C2 C6 C102 C104 C105 C108 C112 C113 C116 C120 C121 C124 C128 C129 C132 C136 C137 C140 C144 C145 C148 C152 C153 C156 = CAP_NP: Not_insert: NI; Part_Type: *LF_C1206
C44 C46 C48 C50 C52 C54 C56 C58 C62 C64 C74 C76 C82 C84 C94 C96 = CAP_NP: Part_Type: *LF_C0805
C45 C51 C55 C59 C65 C77 C85 C97 = CAP_NP: Not_insert: NI; Part_Type: *LF_C0805
C101 C103 C107 C109 C115 C117 C123 C125 C131 C133 C139 C141 C147 C149 C155 C157 = CAP_NP: Not_insert: NI; Part_Type: *LF_C0603
C160 C164-C166 C172-C176 C178 C183-C186 C189-C204 = CAP_NP: Part_Type: *LF_C0402
D2-D9 = LED_0: Part_Type: *LF_Semiconductor
J2-J5 J13-J16 = SCONN29_787280002: Part_Type: *LF_Connector
LED1-LED8 = LED4P_14_23: Part_Type: *LF_Semiconductor
Q1-Q25 = MOSFET_DUAL_6P: Part_Type: *LF_Semiconductor
R1-R5 R8-R12 R73-R78 = R: Part_Type: *LF_Resistor
R6 R7 R13 R14 = R_1: Part_Type: *LF_Resistor
R15 R17 R22 R24 R52 R53 R55 R57-R59 R61-R63 R65 R67 R68 R70 R135 R137 R139-R147 R149 R151-R166 R168-R177 R179 R180 R183 R188 R190 R191 = R: Part_Type: *LF_Resistor; WATTAGE: 1/16W
R16 R18 R23 R25 R96 R97 R99 R100 R116 R117 R119 R120 = R: Part_Type: *LF_Resistor; WATTAGE: 1/4W
R19 R26 = R: Part_Type: *LF_Resistor; WATTAGE: 1/10W
R20 R21 R27 R28 = R_1: Part_Type: *LF_Resistor; WATTAGE: 1/10W
R79-R84 R109-R114 R129-R134 = R: Part_Type: *LF_Resistor; Status: Preferred; WATTAGE: 1/16W
R95 R98 R106 R108 R115 R118 R126 R128 = R: Part_Type: *LF_Resistor; TOP_BOT: TOP; WATTAGE: 1/16W
R101 R107 R121 R127 = R: Part_Type: *LF_Resistor; TOP_BOT: TOP; WATTAGE: 1/10W
R102-R105 R122-R125 = R_1: Part_Type: *LF_Resistor; TOP_BOT: TOP; WATTAGE: 1/10W
C27 C28 C177 C179-C182 C205 C206 = CAP_NP: Part_Type: *LF_C0603
J18 = HEADER2X5S: Part_Type: *LF_Connector
JP2 = HEADER_1X3: Part_Type: *LF_Connector
R138 = R: Part_Type: *LF_Resistor; WATTAGE: 1/20W
U4 = MAX809M: Part_Type: *LF_Chipset
U6 = 74LVC2G14: Part_Type: *LF_Chipset
U9 = MAX_V_5M570ZT100
J9 = IPMB_CONN_1: Part_type: *LF_Connector
U2 = AT24C32: Part_Type: *LF_Chipset
U3 = TMP75AIDR: Part_Type: Chipset
C29 = CAP_NP: Part_Type: *LF_C1206
C30 C31 = CAP_NP: MATERIAL: X7S; Manuf_name: MURATA ERIE N.A. INC TAIWAN BRANCH Okayama Murata Mfg.Co.,Ltd.Wakura Murata Mfg.; Manuftr: MUR; Part_Type: *LF_C1206
C32 C33 = CAP_NP: MATERIAL: X6S; Manuf_name: MURATA ERIE N.A. INC TAIWAN BRANCH Okayama Murata Mfg.Co.,Ltd.Wakura Murata Mfg.; Manuftr: MUR; Part_Type: *LF_C1206
C34-C39 C41-C43 = CAP_NP: MATERIAL: X7R; Manuf_name: AVX CORPARATION CO., LTD.; Manufacturer: AVX; Part_Type: *LF_C0603
C40 = CAP_NP: MATERIAL: X7R; Manuf_name: SAMSUNG ELECTRONICS CO.,LTD; Manuftr: SAM; Part_Type: *LF_C0805
C187 C188 = CAP_NP: MATERIAL: X5R; Manuf_name: MURATA ERIE N.A. INC TAIWAN BRANCH Okayama Murata Mfg.Co..Ltd. Wakura Murata Mfg; Manuftr: MUR; Part_Type: *LF_C1206
CE5 CE6 = CAPACITOR_POL: MATERIAL: OSCON; Manuf_name: SANYO ELECTRIC CO.. LTD. SANYO DENKI CO..LTD; Manuftr: SAY; Part_Type: *LF_C_ELEC_SMD
J11 = CONN10_HM3505E: MATERIAL: IO; Manuf_name: (FOXCON) HON HAI PRECISION IND; Manuftr: FOX; Part_Type: *LF_Connector
U7 = RT9187GQV: Part_Type: *LF_Chipset

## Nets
5V_PRECH_0: J16.P7 R116.2
5V_PRECH_1: J15.P7 R117.2
5V_PRECH_2: J14.P7 R96.2
5V_PRECH_3: J13.P7 R97.2
5V_PRECH_4: J5.P7 R23.2
5V_PRECH_5: J4.P7 R16.2
5V_PRECH_6: J3.P7 R9.2
5V_PRECH_7: J2.P7 R2.2
12V_PRECH_0: J16.P13 R119.2
12V_PRECH_1: J15.P13 R120.2
12V_PRECH_2: J14.P13 R99.2
12V_PRECH_3: J13.P13 R100.2
12V_PRECH_4: J5.P13 R25.2
12V_PRECH_5: J4.P13 R18.2
12V_PRECH_6: J3.P13 R11.2
12V_PRECH_7: J2.P13 R5.2
GND: C1.2 C2.2 C5.2 C6.2 C27.2 C28.2 C29.2 C30.2 C31.2 C32.2 C33.2 C34.2 C35.2 C36.2 C37.2 C38.2 C39.2 C40.2 C41.2 C42.2 C43.2 C44.2 C45.2 C46.2 C48.2 C50.2 C51.2 C52.2 C54.2 C55.2 C56.2 C58.2 C59.2 C62.2 C64.2 C65.2 C74.2 C76.2 C77.2 C82.2 C84.2 C85.2 C94.2 C96.2 C97.2 C100.2 C101.2 C102.2 C103.2 C104.2 C105.2 C106.2 C107.2 C108.2 C109.2 C110.2 C111.2 C112.2 C113.2 C114.2 C115.2 C116.2 C117.2 C118.2 C119.2 C120.2 C121.2 C122.2 C123.2 C124.2 C125.2 C126.2 C127.2 C128.2 C129.2 C130.2 C131.2 C132.2 C133.2 C134.2 C135.2 C136.2 C137.2 C138.2 C139.2 C140.2 C141.2 C142.2 C143.2 C144.2 C145.2 C146.2 C147.2 C148.2 C149.2 C150.2 C151.2 C152.2 C153.2 C154.2 C155.2 C156.2 C157.2 C158.2 C159.2 C160.2 C164.2 C165.2 C166.2 C172.2 C173.2 C174.2 C175.2 C176.2 C177.2 C178.2 C179.2 C180.2 C181.2 C182.2 C183.2 C184.2 C185.2 C186.2 C187.2 C188.2 C189.1 C190.1 C191.1 C192.1 C193.1 C194.1 C195.1 C196.1 C197.1 C198.1 C199.1 C200.1 C201.1 C202.1 C203.1 C204.1 C205.2 C206.2 CE5.2 CE6.2 J2.G1 J2.G2 J2.P4 J2.P6 J2.P10 J2.P12 J2.S1 J2.S4 J2.S7 J2.S8 J2.S11 J2.S14 J3.G1 J3.G2 J3.P4 J3.P6 J3.P10 J3.P12 J3.S1 J3.S4 J3.S7 J3.S8 J3.S11 J3.S14 J4.G1 J4.G2 J4.P4 J4.P6 J4.P10 J4.P12 J4.S1 J4.S4 J4.S7 J4.S8 J4.S11 J4.S14 J5.G1 J5.G2 J5.P4 J5.P6 J5.P10 J5.P12 J5.S1 J5.S4 J5.S7 J5.S8 J5.S11 J5.S14 J9.2 J11.1 J11.2 J11.3 J11.4 J11.5 J13.G1 J13.G2 J13.P4 J13.P6 J13.P10 J13.P12 J13.S1 J13.S4 J13.S7 J13.S8 J13.S11 J13.S14 J14.G1 J14.G2 J14.P4 J14.P6 J14.P10 J14.P12 J14.S1 J14.S4 J14.S7 J14.S8 J14.S11 J14.S14 J15.G1 J15.G2 J15.P4 J15.P6 J15.P10 J15.P12 J15.S1 J15.S4 J15.S7 J15.S8 J15.S11 J15.S14 J16.G1 J16.G2 J16.P4 J16.P6 J16.P10 J16.P12 J16.S1 J16.S4 J16.S7 J16.S8 J16.S11 J16.S14 J17.A3(GND1) J17.A6(GND2) J17.A9(GND3) J17.A12(GND13) J17.A15(GND14) J17.A18(GND15) J17.B3(GND4) J17.B6(GND5) J17.B9(GND6) J17.B12(GND16) J17.B15(GND17) J17.B18(GND18) J17.C3(GND7) J17.C6(GND8) J17.C9(GND9) J17.C12(GND19) J17.C15(GND20) J17.C18(GND21) J17.D3(GND10) J17.D6(GND11) J17.D9(GND12) J17.D12(GND22) J17.D15(GND23) J17.D18(GND24) J17.G1 J17.G2 J17.G3 J17.G4 J17.G5 J17.G6 J18.2 J18.10 JP2.3 Q1.1(S1) Q1.4(S2) Q2.1(S1) Q2.4(S2) Q3.1(S1) Q3.4(S2) Q4.1(S1) Q4.4(S2) Q5.1(S1) Q5.4(S2) Q6.1(S1) Q6.4(S2) Q7.1(S1) Q7.4(S2) Q8.1(S1) Q8.4(S2) Q9.1(S1) Q9.4(S2) Q10.1(S1) Q10.4(S2) Q11.1(S1) Q11.4(S2) Q12.1(S1) Q12.4(S2) Q13.1(S1) Q13.4(S2) Q14.1(S1) Q14.4(S2) Q15.1(S1) Q15.4(S2) Q16.1(S1) Q16.4(S2) Q17.1(S1) Q17.4(S2) Q18.1(S1) Q18.4(S2) Q19.1(S1) Q19.4(S2) Q20.1(S1) Q20.4(S2) Q21.1(S1) Q21.4(S2) Q22.1(S1) Q22.4(S2) Q23.1(S1) Q23.4(S2) Q24.1(S1) Q24.4(S2) R59.2 R60.2 R61.2 R62.2 R68.2 R69.2 R70.2 R138.2 R148.1 R149.1 R189.1 R191.2 U2.4(GND) U3.4(GND) U4.1(GND) U6.2(GND) U7.6(GND) U7.TH(EP) U9.8(GND1) U9.10(GND2) U9.11(GND3) U9.32(GND4) U9.37(GND5) U9.46(GND6) U9.60(GND7) U9.65(GND8) U9.79(GND9) U9.90(GND10) U9.93(GND11) U9.95(GND12)
P1V8: C166.1 C173.1 C184.1 C186.1 C206.1 R190.1 U7.3(VOUT_1) U7.4(VOUT_2) U9.13(VCCINT1) U9.39(VCCINT2) U9.63(VCCINT3) U9.88(VCCINT4)
P3V3: C40.1 C41.1 C42.1 C43.1 C164.1 C165.1 C172.1 C174.1 C175.1 C179.1 C180.1 C181.1 C182.1 C183.1 C185.1 C205.1 J11.10 J18.4 LED1.1(D1) LED2.1(D1) LED3.1(D1) LED4.1(D1) LED5.1(D1) LED6.1(D1) LED7.1(D1) LED8.1(D1) Q25.2(G1) Q25.5(G2) R1.2 R3.2 R8.2 R10.2 R15.2 R17.2 R22.2 R24.2 R52.1 R53.1 R73.1 R74.1 R75.1 R76.1 R77.1 R78.1 R79.1 R80.1 R81.1 R82.1 R83.1 R84.1 R95.2 R98.2 R106.2 R108.2 R109.1 R110.1 R111.1 R112.1 R113.1 R114.1 R115.2 R118.2 R126.2 R128.2 R129.1 R130.1 R131.1 R132.1 R133.1 R134.1 R135.1 R137.2 R139.2 R140.2 R141.2 R142.2 R143.2 R144.2 R145.2 R146.1 R147.1 R151.1 R152.1 R153.1 R154.1 R155.1 R156.1 R157.1 R158.1 R159.1 R160.1 R161.1 R162.1 R163.1 R164.1 R165.1 R166.1 R169.1 R170.1 R171.1 R172.1 R173.1 R174.1 R175.1 R176.1 R183.1 R188.2 R196.2 R197.2 R198.2 R199.2 R200.2 R201.2 R202.2 R203.2 U6.5(VCC) U7.1(VIN) U7.2(VIN) U9.9(VCCIO1) U9.31(VCCIO1) U9.45(VCCIO1) U9.59(VCCIO2) U9.80(VCCIO2) U9.94(VCCIO2)
P3V3_STBY: C27.1 C28.1 C177.1 C178.1 J9.4 R54.2 R55.2 R56.2 R64.2 R65.2 R66.2 U2.8(VCC) U3.8(VCC)
P5V: C5.1 C6.1 C32.1 C33.1 C37.1 C38.1 C39.1 C44.1 C48.1 C52.1 C56.1 C62.1 C74.1 C82.1 C94.1 C100.1 C101.1 C104.1 C106.1 C107.1 C111.1 C112.1 C114.1 C115.1 C119.1 C120.1 C122.1 C123.1 C127.1 C128.1 C130.1 C131.1 C135.1 C136.1 C138.1 C139.1 C143.1 C144.1 C146.1 C147.1 C151.1 C152.1 C154.1 C155.1 C159.1 C187.1 C188.1 C190.2 C192.2 C194.2 C196.2 C198.2 C200.2 C202.2 C204.2 CE6.1 D2.A D3.A D4.A D5.A D6.A D7.A D8.A D9.A J2.P8 J2.P9 J3.P8 J3.P9 J4.P8 J4.P9 J5.P8 J5.P9 J11.8 J11.9 J13.P8 J13.P9 J14.P8 J14.P9 J15.P8 J15.P9 J16.P8 J16.P9 LED1.2(D2) LED2.2(D2) LED3.2(D2) LED4.2(D2) LED5.2(D2) LED6.2(D2) LED7.2(D2) LED8.2(D2) R2.1 R9.1 R16.1 R23.1 R96.1 R97.1 R116.1 R117.1
P12V: C1.1 C2.1 C29.1 C30.1 C31.1 C34.1 C35.1 C36.1 C45.1 C46.1 C50.1 C51.1 C54.1 C55.1 C58.1 C59.1 C64.1 C65.1 C76.1 C77.1 C84.1 C85.1 C96.1 C97.1 C102.1 C103.1 C105.1 C108.1 C109.1 C110.1 C113.1 C116.1 C117.1 C118.1 C121.1 C124.1 C125.1 C126.1 C129.1 C132.1 C133.1 C134.1 C137.1 C140.1 C141.1 C142.1 C145.1 C148.1 C149.1 C150.1 C153.1 C156.1 C157.1 C158.1 C189.2 C191.2 C193.2 C195.2 C197.2 C199.2 C201.2 C203.2 CE5.1 J2.P14 J2.P15 J3.P14 J3.P15 J4.P14 J4.P15 J5.P14 J5.P15 J11.6 J11.7 J13.P14 J13.P15 J14.P14 J14.P15 J15.P14 J15.P15 J16.P14 J16.P15 R5.1 R11.1 R18.1 R25.1 R99.1 R100.1 R119.1 R120.1
VCC_RESET: C160.1 R135.2 U4.3(VCC)
CLK_2M_CPLD: U6.6(1Y) U9.62(IO_2_62/CLK2)
CLK_2M_CPLD_BUFF: C176.1 R168.1 U6.3(2A)
CLK_2M_CPLD_N: R168.2 R179.2 U6.4(2Y)
CLK_2M_CPLD_R_N: R179.1 U6.1(1A)
CODE_SELET_CPLD_N: JP2.2 U9.34(IO_1_34/DIFFIO_B3N)
CPLD_HDD0_ACT_N: Q22.2(G1) R166.2 U9.5(IO_1_5/DIFFIO_L2N)
CPLD_HDD0_FAULT_N: Q24.2(G1) R165.2 U9.4(IO_1_4/DIFFIO_L2P)
CPLD_HDD0_LOC_N: Q23.2(G1) R170.2 U9.91(IO_2_91/DIFFIO_T4N)
CPLD_HDD1_ACT_N: Q19.2(G1) R152.2 U9.16(IO_1_16/DIFFIO_L4N)
CPLD_HDD1_FAULT_N: Q21.2(G1) R151.2 U9.15(IO_1_15/DIFFIO_L4P)
CPLD_HDD1_LOC_N: Q20.2(G1) R172.2 U9.92(IO_2_92/DIFFIO_T4P)
CPLD_HDD2_ACT_N: Q16.2(G1) R154.2 U9.21(IO_1_21/DIFFIO_L6N)
CPLD_HDD2_FAULT_N: Q18.2(G1) R153.2 U9.20(IO_1_20/DIFFIO_L6P)
CPLD_HDD2_LOC_N: Q17.2(G1) R171.2 U9.89(IO_2_89/DIFFIO_T5P)
CPLD_HDD3_ACT_N: Q13.2(G1) R156.2 U9.30(IO_1)
CPLD_HDD3_FAULT_N: Q15.2(G1) R155.2 U9.29(IO_1_29/DIFFIO_B2N)
CPLD_HDD3_LOC_N: Q14.2(G1) R173.2 U9.96(IO_2_96/DIFFIO_T3N)
CPLD_HDD4_ACT_N: Q10.2(G1) R158.2 U9.48(IO_1_48/DIFFIO_B8N)
CPLD_HDD4_FAULT_N: Q12.2(G1) R157.2 U9.47(IO_1_47/DIFFIO_B8P)
CPLD_HDD4_LOC_N: Q11.2(G1) R174.2 U9.97(IO_2_97/DIFFIO_T3P)
CPLD_HDD5_ACT_N: Q7.2(G1) R160.2 U9.44(IO_1_44/DEV_CLRN/DIFFIO_B7N)
CPLD_HDD5_FAULT_N: Q9.2(G1) R159.2 U9.43(IO_1_43/DEV_OE/DIFFIO_B7P)
CPLD_HDD5_LOC_N: Q8.2(G1) R175.2 U9.98(IO_2_98/DIFFIO_T2N)
CPLD_HDD6_ACT_N: Q4.2(G1) R162.2 U9.55(IO_2_55/DIFFIO_R5N)
CPLD_HDD6_FAULT_N: Q6.2(G1) R161.2 U9.54(IO_2_54/DIFFIO_R6P)
CPLD_HDD6_LOC_N: Q5.2(G1) R176.2 U9.99(IO_2_99/DIFFIO_T2P)
CPLD_HDD7_ACT_N: Q1.2(G1) R164.2 U9.66(IO_2_66/DIFFIO_R3N)
CPLD_HDD7_FAULT_N: Q3.2(G1) R163.2 U9.61(IO_2)
CPLD_HDD7_LOC_N: Q2.2(G1) R169.2 U9.100(IO_2_100/DIFFIO_T1N)
CPLD_J17A_SB0: R72.2 R200.1 U9.67(IO_2_67/DIFFIO_R3P)
CPLD_J17A_SB1: R194.2 R201.1 U9.68(IO_2)
CPLD_J17A_SB4: R195.1 R202.1 U9.69(IO_2)
CPLD_J17A_SB5: R71.1 R203.1 U9.70(IO_2)
CPLD_J17B_SB0: R94.2 R198.1 U9.85(IO_2_85/DIFFIO_T6N)
CPLD_J17B_SB1: R193.2 R199.1 U9.86(IO_2_86/DIFFIO_T6P)
CPLD_J17B_SB4: R192.1 R196.1 U9.83(IO_2_83/DIFFIO_T7N)
CPLD_J17B_SB5: R93.1 R197.1 U9.84(IO_2_84/DIFFIO_T7P)
CPLD_PWRGD: R138.1 R177.1 U4.2(RESET#)
CPLD_PWRGD_R: R177.2 U9.36(IO_1_36/DIFFIO_B4N)
CPLD_TCK: J18.1 R149.2 U9.24(TCK)
CPLD_TDI: J18.9 R147.2 U9.23(TDI)
CPLD_TDO: J18.3 R148.2 R180.1
CPLD_TDO_R: R180.2 U9.25(TDO)
CPLD_TMS: J18.5 R146.2 U9.22(TMS)
FRU_A0: R54.1 R59.1 U2.1(A0)
FRU_A1: R55.1 R60.1 U2.2(A1)
FRU_A2: R56.1 R61.1 U2.3(A2)
HDD0_ACT: D7.C R121.2
HDD0_ACT_N: J16.P11 R115.1 U9.2(IO_1_2/DIFFIO_L1P)
HDD0_ACT_R: Q22.3(D2) R121.1
HDD0_FAULT: LED8.4 R125.2
HDD0_FAULT_R: Q24.3(D2) R125.1
HDD0_LOC: LED8.3 R123.2
HDD0_LOC_R: Q23.3(D2) R123.1
HDD0_PRSNT_N: J16.P5 R128.1 U9.3(IO_1_3/DIFFIO_L1N)
HDD1_ACT: D8.C R127.2
HDD1_ACT_N: J15.P11 R118.1 U9.7(IO_1_7/DIFFIO_L3N)
HDD1_ACT_R: Q19.3(D2) R127.1
HDD1_FAULT: LED7.4 R124.2
HDD1_FAULT_R: Q21.3(D2) R124.1
HDD1_LOC: LED7.3 R122.2
HDD1_LOC_R: Q20.3(D2) R122.1
HDD1_PRSNT_N: J15.P5 R126.1 U9.6(IO_1_6/DIFFIO_L3P)
HDD2_ACT: D5.C R101.2
HDD2_ACT_N: J14.P11 R95.1 U9.18(IO_1_18/DIFFIO_L5N)
HDD2_ACT_R: Q16.3(D2) R101.1
HDD2_FAULT: LED6.4 R105.2
HDD2_FAULT_R: Q18.3(D2) R105.1
HDD2_LOC: LED6.3 R103.2
HDD2_LOC_R: Q17.3(D2) R103.1
HDD2_PRSNT_N: J14.P5 R108.1 U9.19(IO_1)
HDD3_ACT: D6.C R107.2
HDD3_ACT_N: J13.P11 R98.1 U9.27(IO_1_27/DIFFIO_B1N)
HDD3_ACT_R: Q13.3(D2) R107.1
HDD3_FAULT: LED5.4 R104.2
HDD3_FAULT_R: Q15.3(D2) R104.1
HDD3_LOC: LED5.3 R102.2
HDD3_LOC_R: Q14.3(D2) R102.1
HDD3_PRSNT_N: J13.P5 R106.1 U9.28(IO_1_28/DIFFIO_B2P)
HDD4_ACT: D4.C R26.2
HDD4_ACT_N: J5.P11 R24.1 U9.41(IO_1_41/DIFFIO_B6P)
HDD4_ACT_R: Q10.3(D2) R26.1
HDD4_FAULT: LED4.4 R28.2
HDD4_FAULT_R: Q12.3(D2) R28.1
HDD4_LOC: LED4.3 R27.2
HDD4_LOC_R: Q11.3(D2) R27.1
HDD4_PRSNT_N: J5.P5 R22.1 U9.42(IO_1_42/DIFFIO_B6N)
HDD5_ACT: D3.C R19.2
HDD5_ACT_N: J4.P11 R17.1 U9.50(IO_1)
HDD5_ACT_R: Q7.3(D2) R19.1
HDD5_FAULT: LED3.4 R21.2
HDD5_FAULT_R: Q9.3(D2) R21.1
HDD5_LOC: LED3.3 R20.2
HDD5_LOC_R: Q8.3(D2) R20.1
HDD5_PRSNT_N: J4.P5 R15.1 U9.51(IO_1)
HDD6_ACT: D2.C R12.2
HDD6_ACT_N: J3.P11 R10.1 U9.52(IO_2)
HDD6_ACT_R: Q4.3(D2) R12.1
HDD6_FAULT: LED2.4 R14.2
HDD6_FAULT_R: Q6.3(D2) R14.1
HDD6_LOC: LED2.3 R13.2
HDD6_LOC_R: Q5.3(D2) R13.1
HDD6_PRSNT_N: J3.P5 R8.1 U9.53(IO_2_53/DIFFIO_R6N)
HDD7_ACT: D9.C R4.2
HDD7_ACT_N: J2.P11 R3.1 U9.57(IO_2_57/DIFFIO_R4N)
HDD7_ACT_R: Q1.3(D2) R4.1
HDD7_FAULT: LED1.4 R7.2
HDD7_FAULT_R: Q3.3(D2) R7.1
HDD7_LOC: LED1.3 R6.2
HDD7_LOC_R: Q2.3(D2) R6.1
HDD7_PRSNT_N: J2.P5 R1.1 U9.58(IO_2_58/DIFFIO_R4P)
I2C_TMP75_0_A0: R64.1 R68.1 U3.7(A0)
I2C_TMP75_0_A1: R65.1 R69.1 U3.6(A1)
I2C_TMP75_0_A2: R66.1 R70.1 U3.5(A2)
SATA_RX_DN0: J16.S5 J17.D14(TX4-)
SATA_RX_DN1: J15.S5 J17.C14(TX5-)
SATA_RX_DN2: J14.S5 J17.D17(TX6-)
SATA_RX_DN3: J13.S5 J17.C17(TX7-)
SATA_RX_DN4: J5.S5 J17.D5(TX0-)
SATA_RX_DN5: J4.S5 J17.C5(TX1-)
SATA_RX_DN6: J3.S5 J17.D8(TX2-)
SATA_RX_DN7: J2.S5 J17.C8(TX3-)
SATA_RX_DP0: J16.S6 J17.D13(TX4+)
SATA_RX_DP1: J15.S6 J17.C13(TX5+)
SATA_RX_DP2: J14.S6 J17.D16(TX6+)
SATA_RX_DP3: J13.S6 J17.C16(TX7+)
SATA_RX_DP4: J5.S6 J17.D4(TX0+)
SATA_RX_DP5: J4.S6 J17.C4(TX1+)
SATA_RX_DP6: J3.S6 J17.D7(TX2+)
SATA_RX_DP7: J2.S6 J17.C7(TX3+)
SATA_TX_DN0: J16.S3 J17.B14(RX4-)
SATA_TX_DN1: J15.S3 J17.A14(RX5-)
SATA_TX_DN2: J14.S3 J17.B17(RX6-)
SATA_TX_DN3: J13.S3 J17.A17(RX7-)
SATA_TX_DN4: J5.S3 J17.B5(RX0-)
SATA_TX_DN5: J4.S3 J17.A5(RX1-)
SATA_TX_DN6: J3.S3 J17.B8(RX2-)
SATA_TX_DN7: J2.S3 J17.A8(RX3-)
SATA_TX_DP0: J16.S2 J17.B13(RX4+)
SATA_TX_DP1: J15.S2 J17.A13(RX5+)
SATA_TX_DP2: J14.S2 J17.B16(RX6+)
SATA_TX_DP3: J13.S2 J17.A16(RX7+)
SATA_TX_DP4: J5.S2 J17.B4(RX0+)
SATA_TX_DP5: J4.S2 J17.A4(RX1+)
SATA_TX_DP6: J3.S2 J17.B7(RX2+)
SATA_TX_DP7: J2.S2 J17.A7(RX3+)
SGPIO_SCLK_A: J17.A10(SB15) R140.1 U9.75(IO_2)
SGPIO_SCLK_B: J17.A1(SB7) R144.1 U9.81(IO_2)
SGPIO_SDI_A: J17.D11(SB14) R141.1 U9.76(IO_2)
SGPIO_SDI_B: J17.D2(SB6) R145.1 U9.82(IO_2)
SGPIO_SDO_A: J17.C11(SB10) R139.1 U9.74(IO_2_74/DIFFIO_R1P)
SGPIO_SDO_B: J17.C2(SB2) R143.1 U9.78(IO_2_78/DIFFIO_T8P)
SGPIO_SLOAD_A: J17.B10(SB11) R137.1 U9.73(IO_2_73/DIFFIO_R1N)
SGPIO_SLOAD_B: J17.B1(SB3) R142.1 U9.77(IO_2_77/DIFFIO_T8N)
SMB_AMI_3VSB_CLK: J9.3 Q25.6(D1) R57.2 R67.1
SMB_AMI_3VSB_DAT: J9.1 Q25.3(D2) R58.2 R63.1
SMB_AMI_P3V3_CLK: Q25.1(S1) R52.2 U9.14(IO_1_14/CLK1)
SMB_AMI_P3V3_DAT: Q25.4(S2) R53.2 U9.12(IO_1_12/CLK0)
SMB_IPMB_3V_FRU_CLK: R57.1 U2.6(SCL)
SMB_IPMB_3V_FRU_DAT: R58.1 U2.5(SDA)
SMB_IPMB_3V_TMP_CLK: R67.2 U3.2(SCL)
SMB_IPMB_3V_TMP_DAT: R63.2 U3.1(SDA)
WP_CONTORL: R62.1 U2.7(WP)
N3991939: Q1.5(G2) Q1.6(D1) R73.2
N3993005: Q2.5(G2) Q2.6(D1) R74.2
N3993407: Q3.5(G2) Q3.6(D1) R75.2
N3995821: Q4.5(G2) Q4.6(D1) R76.2
N3995929: Q5.5(G2) Q5.6(D1) R77.2
N3996045: Q6.5(G2) Q6.6(D1) R78.2
N4003046: Q7.5(G2) Q7.6(D1) R79.2
N4003154: Q8.5(G2) Q8.6(D1) R80.2
N4003270: Q9.5(G2) Q9.6(D1) R81.2
N4004123: Q10.5(G2) Q10.6(D1) R82.2
N4004231: Q11.5(G2) Q11.6(D1) R83.2
N4004343: Q12.5(G2) Q12.6(D1) R84.2
N4035676: Q13.5(G2) Q13.6(D1) R109.2
N4035920: Q14.5(G2) Q14.6(D1) R110.2
N4036036: Q15.5(G2) Q15.6(D1) R111.2
N4036232: Q16.5(G2) Q16.6(D1) R112.2
N4036324: Q17.5(G2) Q17.6(D1) R113.2
N4036440: Q18.5(G2) Q18.6(D1) R114.2
N4041634: Q19.5(G2) Q19.6(D1) R129.2
N4041878: Q20.5(G2) Q20.6(D1) R130.2
N4041994: Q21.5(G2) Q21.6(D1) R131.2
N4042190: Q22.5(G2) Q22.6(D1) R132.2
N4042282: Q23.5(G2) Q23.6(D1) R133.2
N4042398: Q24.5(G2) Q24.6(D1) R134.2
N4262219: J17.D10(SB13) R93.2
N4262930: J17.A11(SB8) R94.1
N4263411: J17.D1(SB5) R71.2
N4264116: J17.A2(SB0) R72.1
N4616523: JP2.1 R183.2
N4634730: R188.1 R189.2 U7.8(EN)
N4634734: R190.2 R191.1 U7.5(ADJ)
N4678612: J17.B2(SB1) R194.1
N4679260: J17.C1(SB4) R195.2
N4679298: J17.C10(SB12) R192.2
N4679336: J17.B11(SB9) R193.1

Not connected (* = marked no-connect by the designer): J2 P1 P2 P3 S9 S10 S12 S13; J3 P1 P2 P3 S9 S10 S12 S13; J4 P1 P2 P3 S9 S10 S12 S13; J5 P1 P2 P3 S9 S10 S12 S13; J13 P1 P2 P3 S9 S10 S12 S13; J14 P1 P2 P3 S9 S10 S12 S13; J15 P1 P2 P3 S9 S10 S12 S13; J16 P1 P2 P3 S9 S10 S12 S13; J18 6 7 8; U3 3(ALERT); U7 7(NC); U9 1(IO_2_1/DIFFIO_T1P) 17(IO_1_17/DIFFIO_L5P) 26(IO_1_26/DIFFIO_B1P) 33(IO_1_33/DIFFIO_B3P) 35(IO_1_35/DIFFIO_B4P) 38(IO_1_38/DIFFIO_B5P) 40(IO_1_40/DIFFIO_B5N) 49(IO_1) 56(IO_2_56/DIFFIO_R5P) 64(IO_2_64/CLK3) 71(IO_2_71/DIFFIO_R2N) 72(IO_2_72/DIFFIO_R2P) 87(IO_2_87/DIFFIO_T5N)

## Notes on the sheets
sheet 1
- Big Sur_HDD_BP_Board
- PAGE #
- DESCRIPTION
- P01 Cover Page
  P02 Mini SAS connector
  P03 HDD Conn 76
  P04 HDD Conn 54
  P05 HDD Conn 32
  P06 HDD Conn 10
  P07 CPLD
  P08 FRU & TMP SENSORS
  P09 HDD PCON & CAP
  P10 P1V8
